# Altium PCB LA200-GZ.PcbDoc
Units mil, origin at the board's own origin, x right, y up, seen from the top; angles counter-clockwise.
Board outline 3789.56 x 3553.34 mil, 4 copper layers (Top Layer, GND, VCC, Bottom Layer), stack 30.634 mil thick; 139 components, 86 nets, 416 pads, 289 vias.
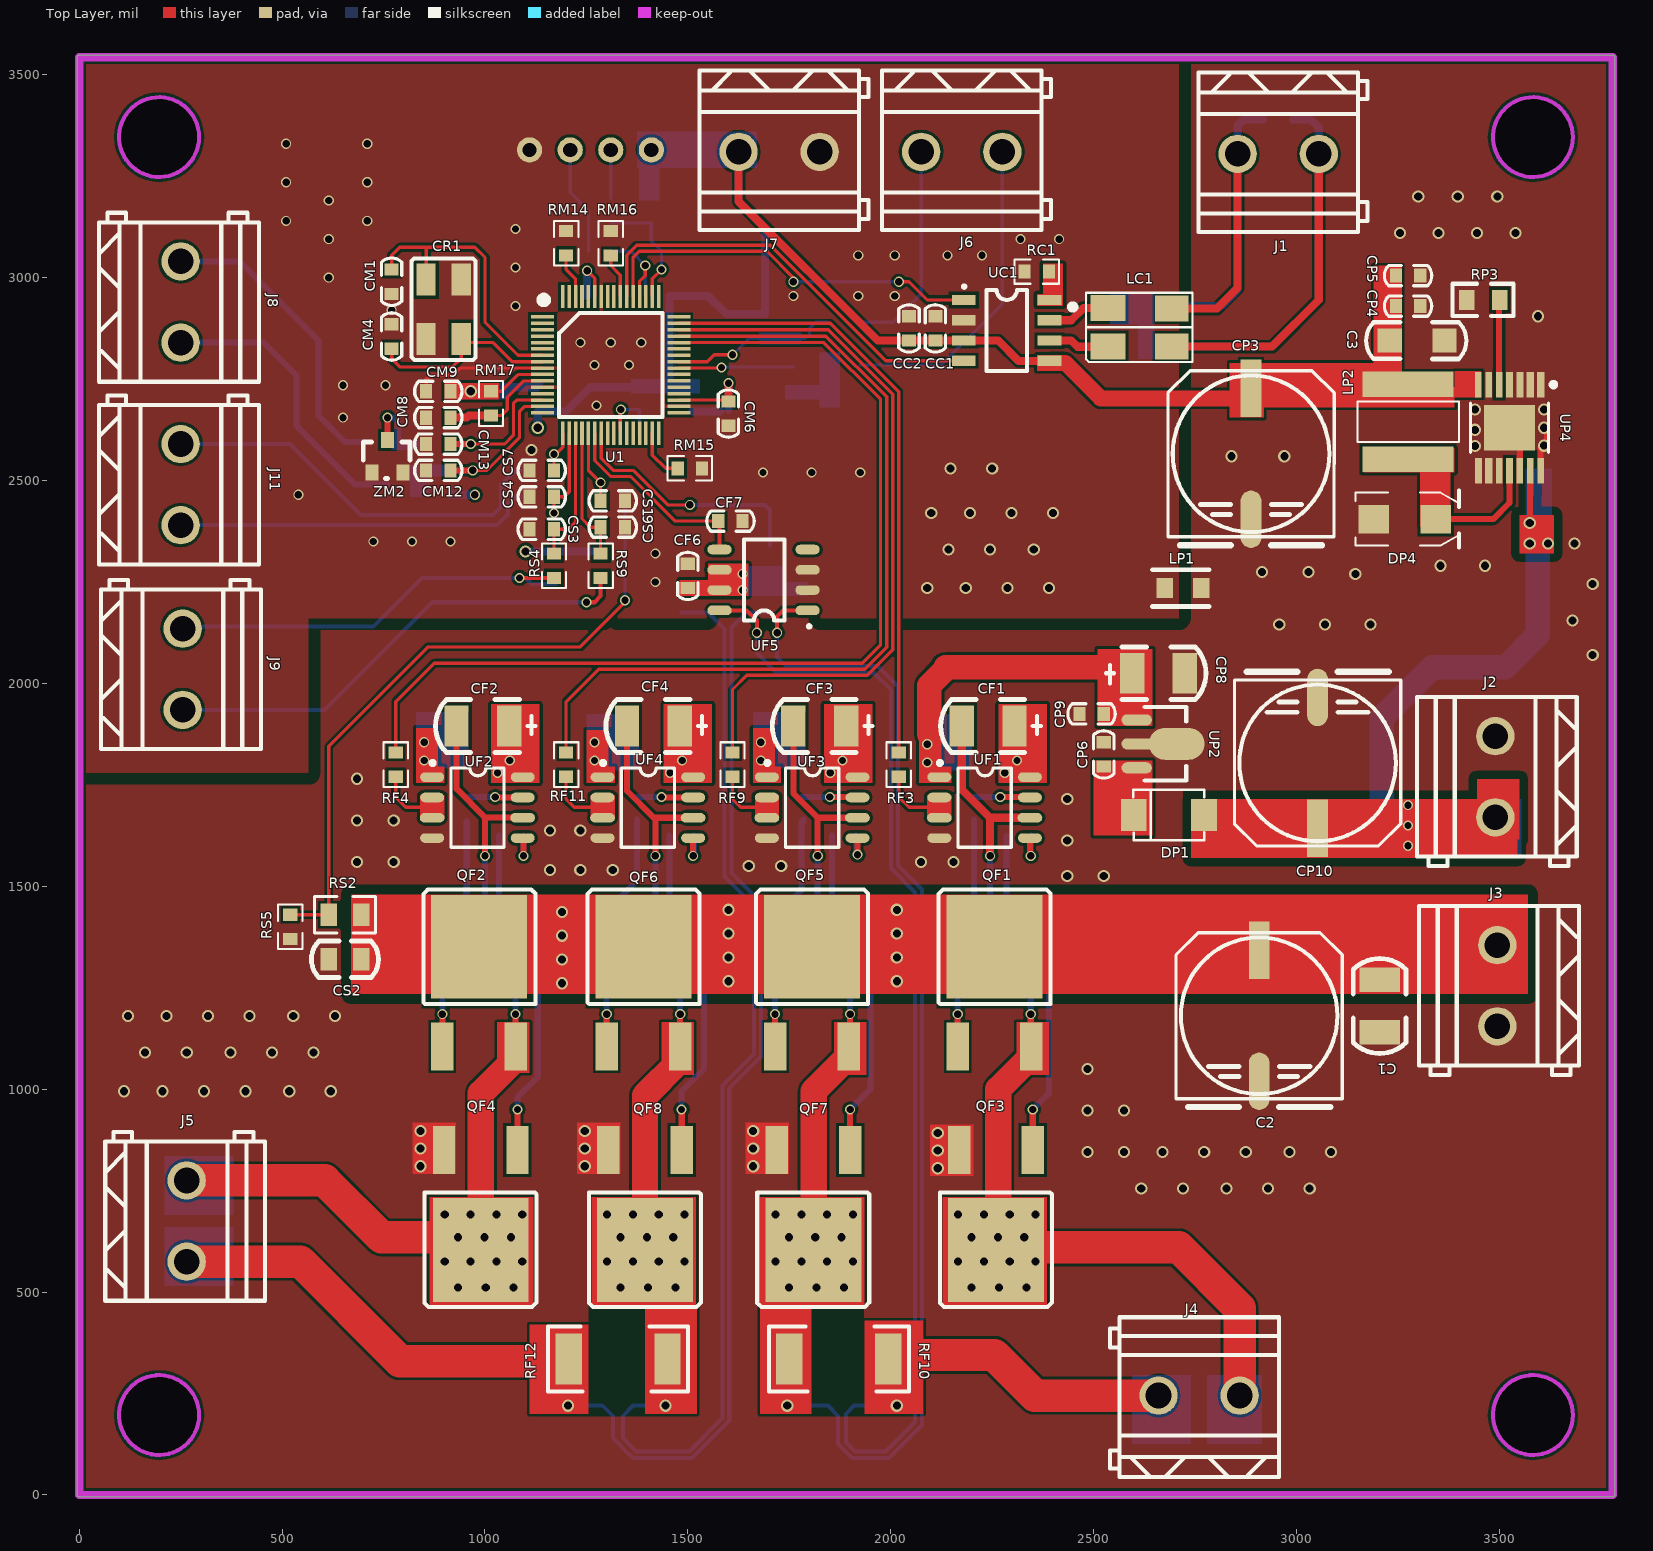
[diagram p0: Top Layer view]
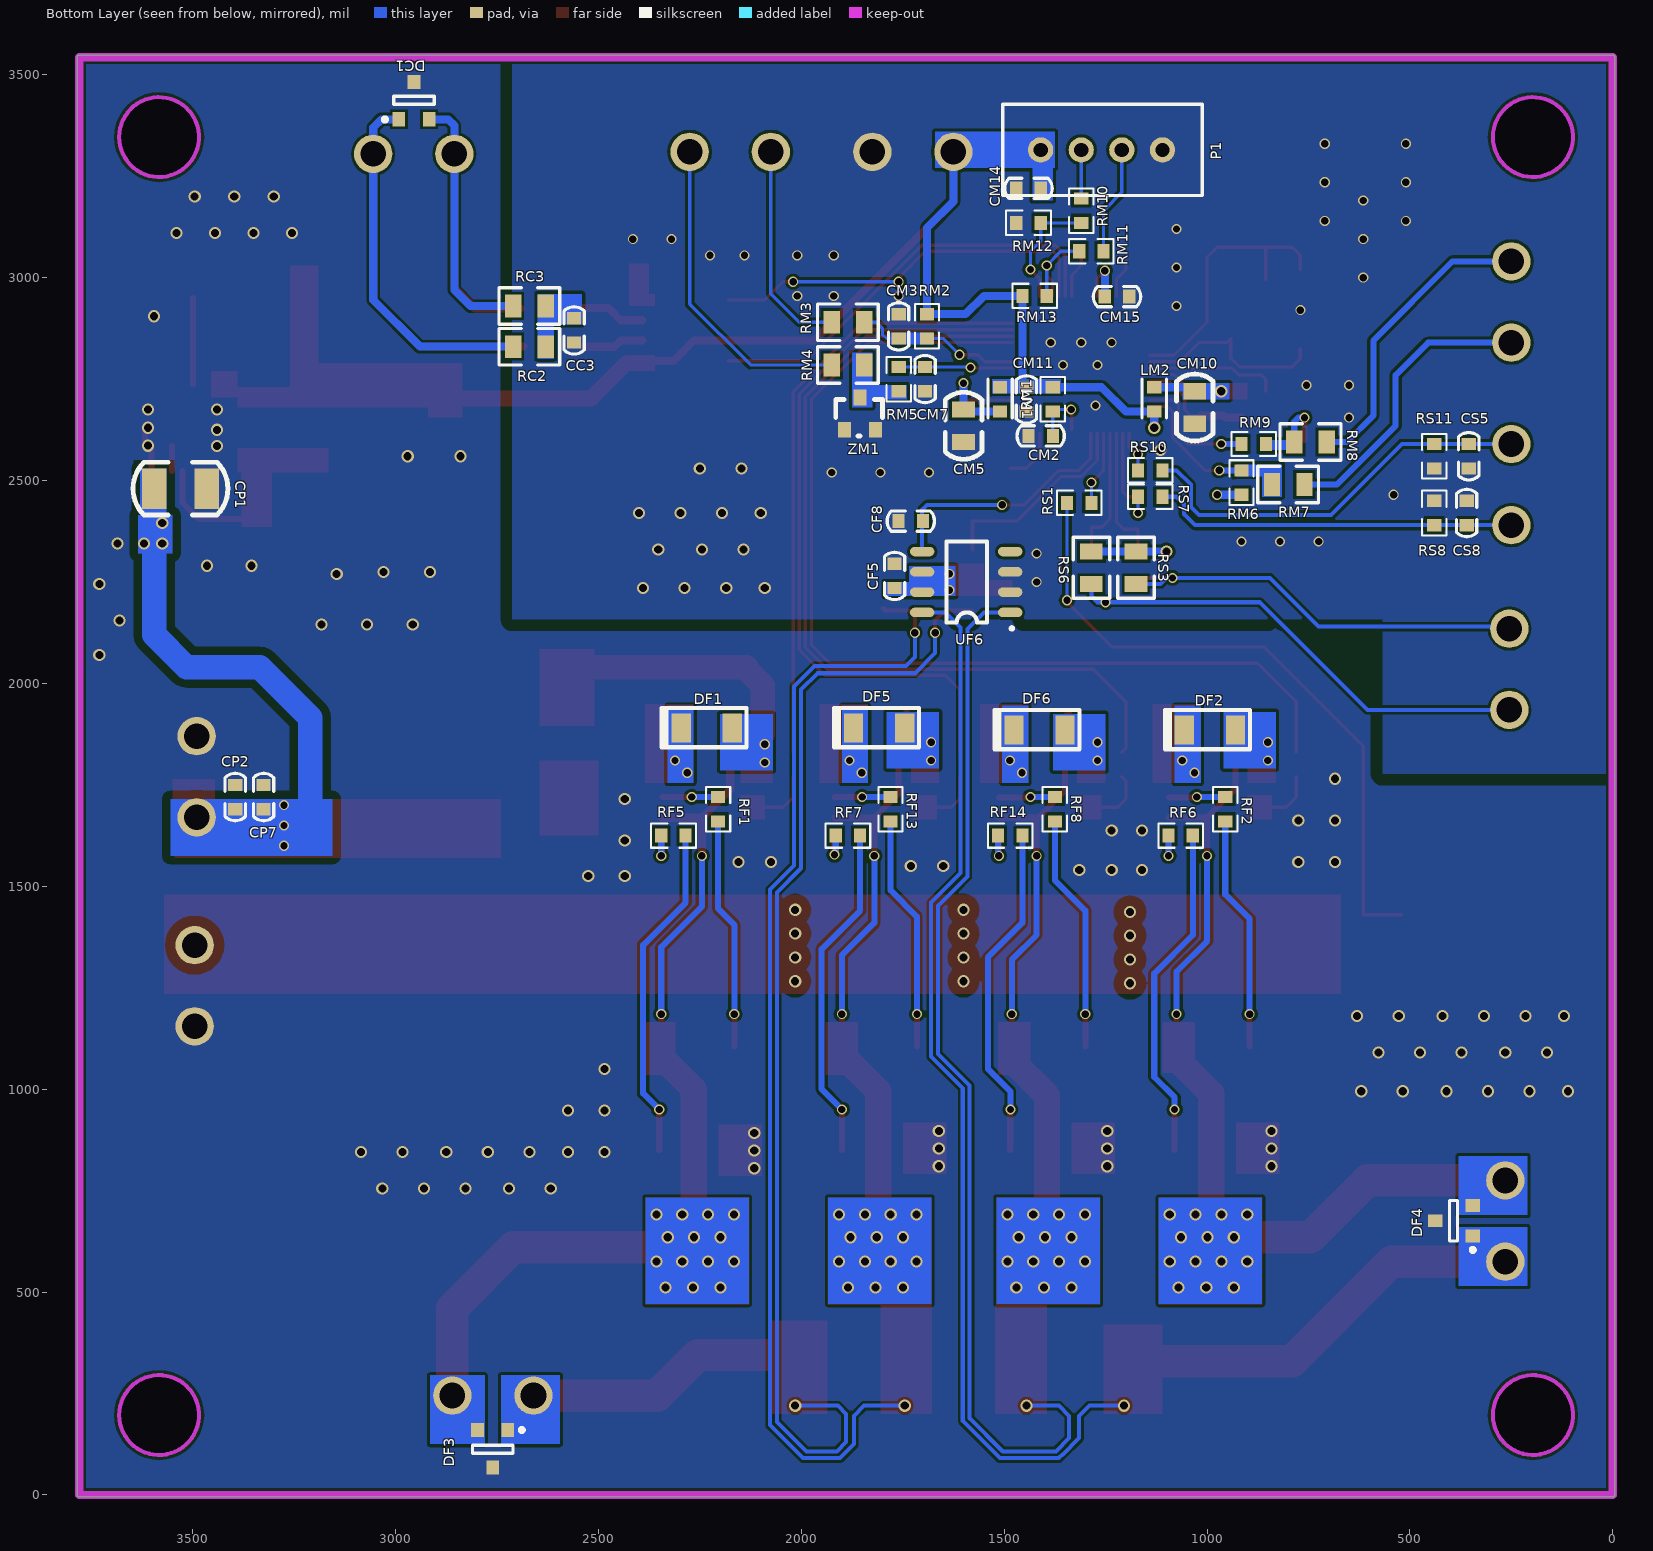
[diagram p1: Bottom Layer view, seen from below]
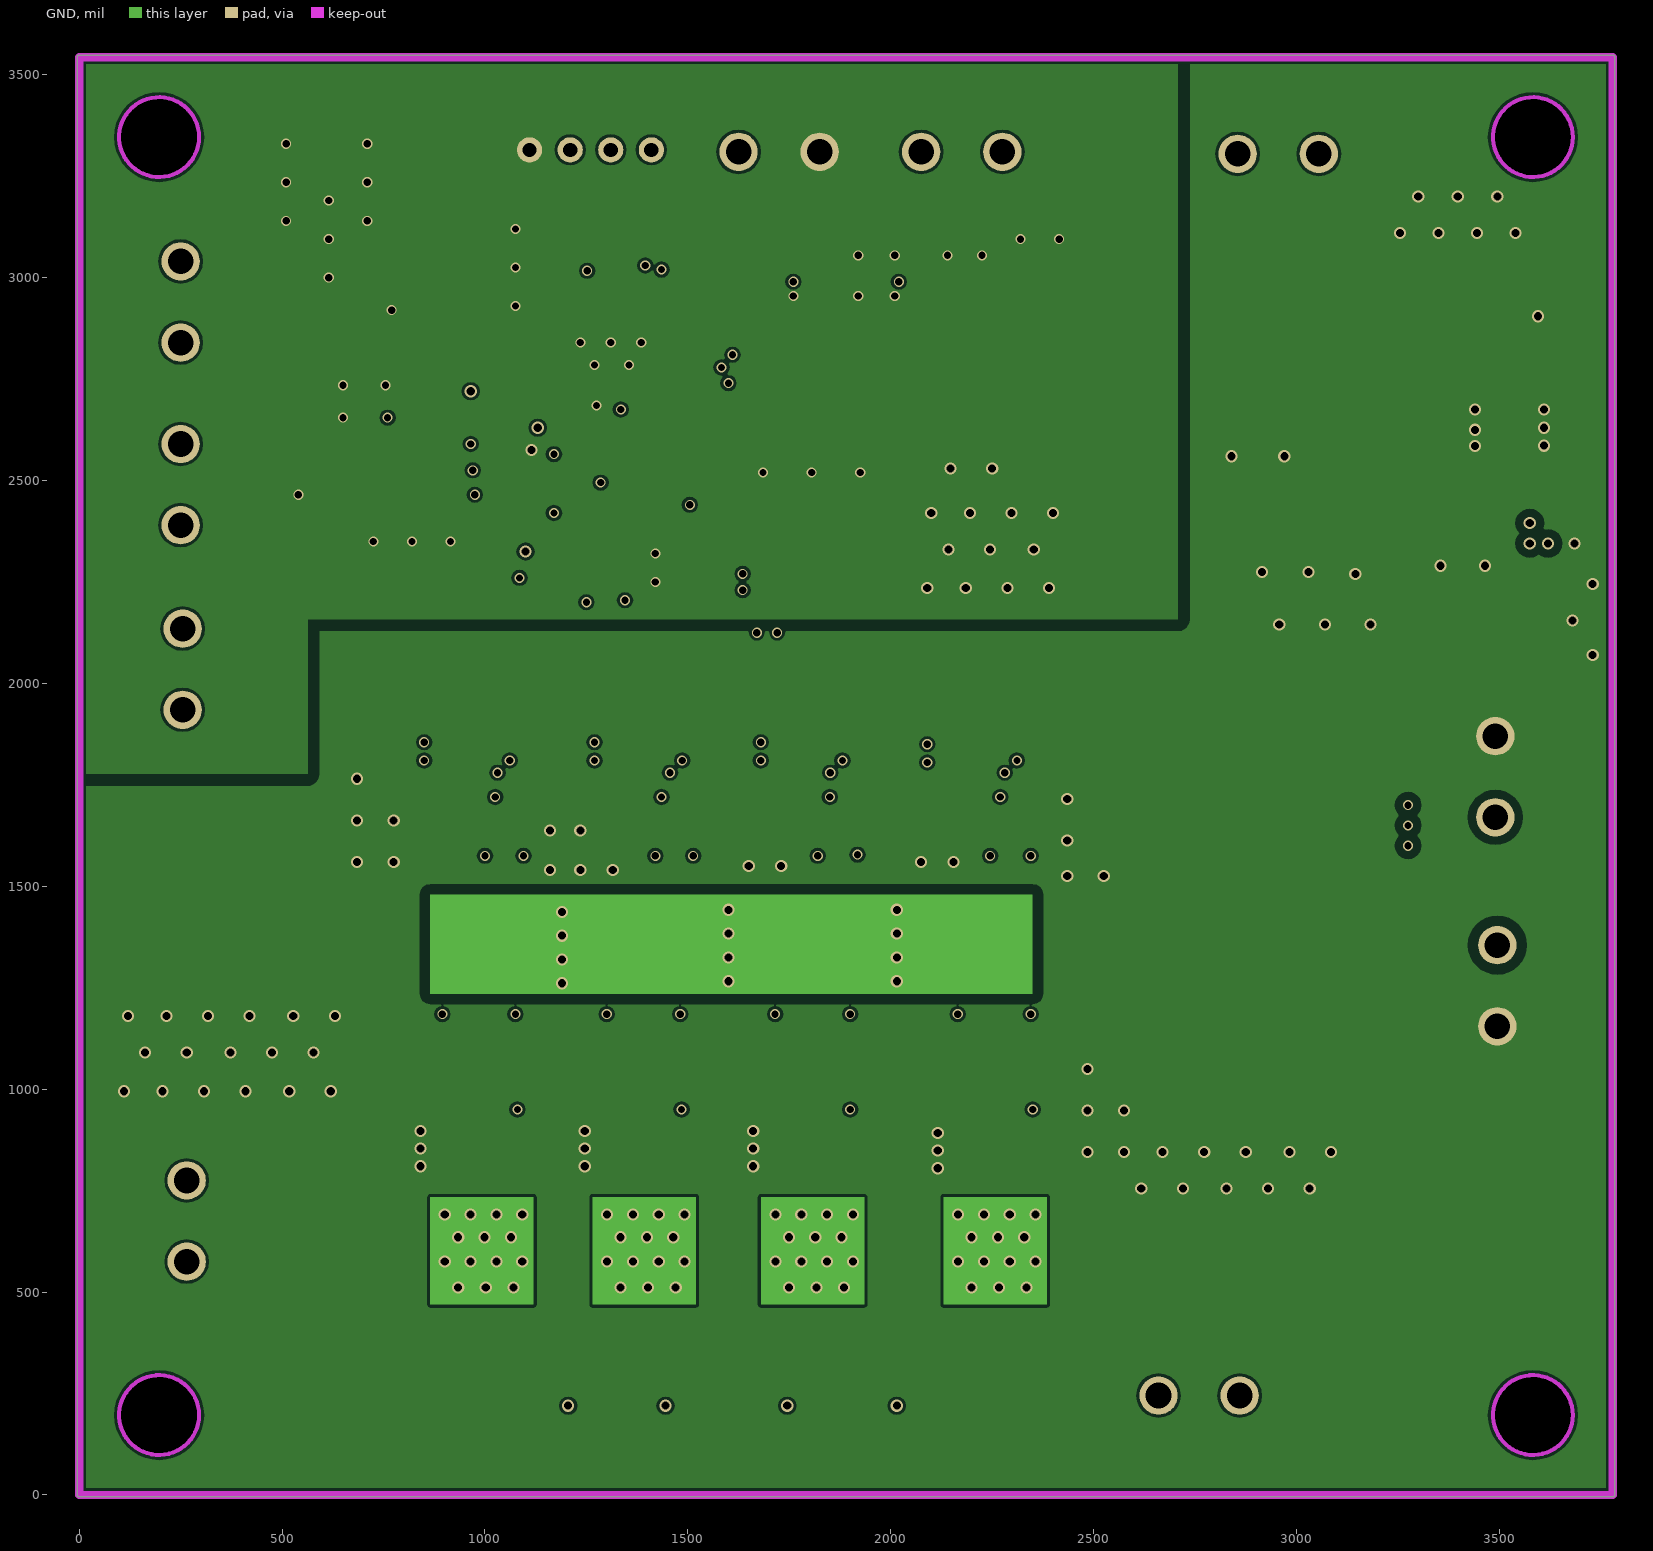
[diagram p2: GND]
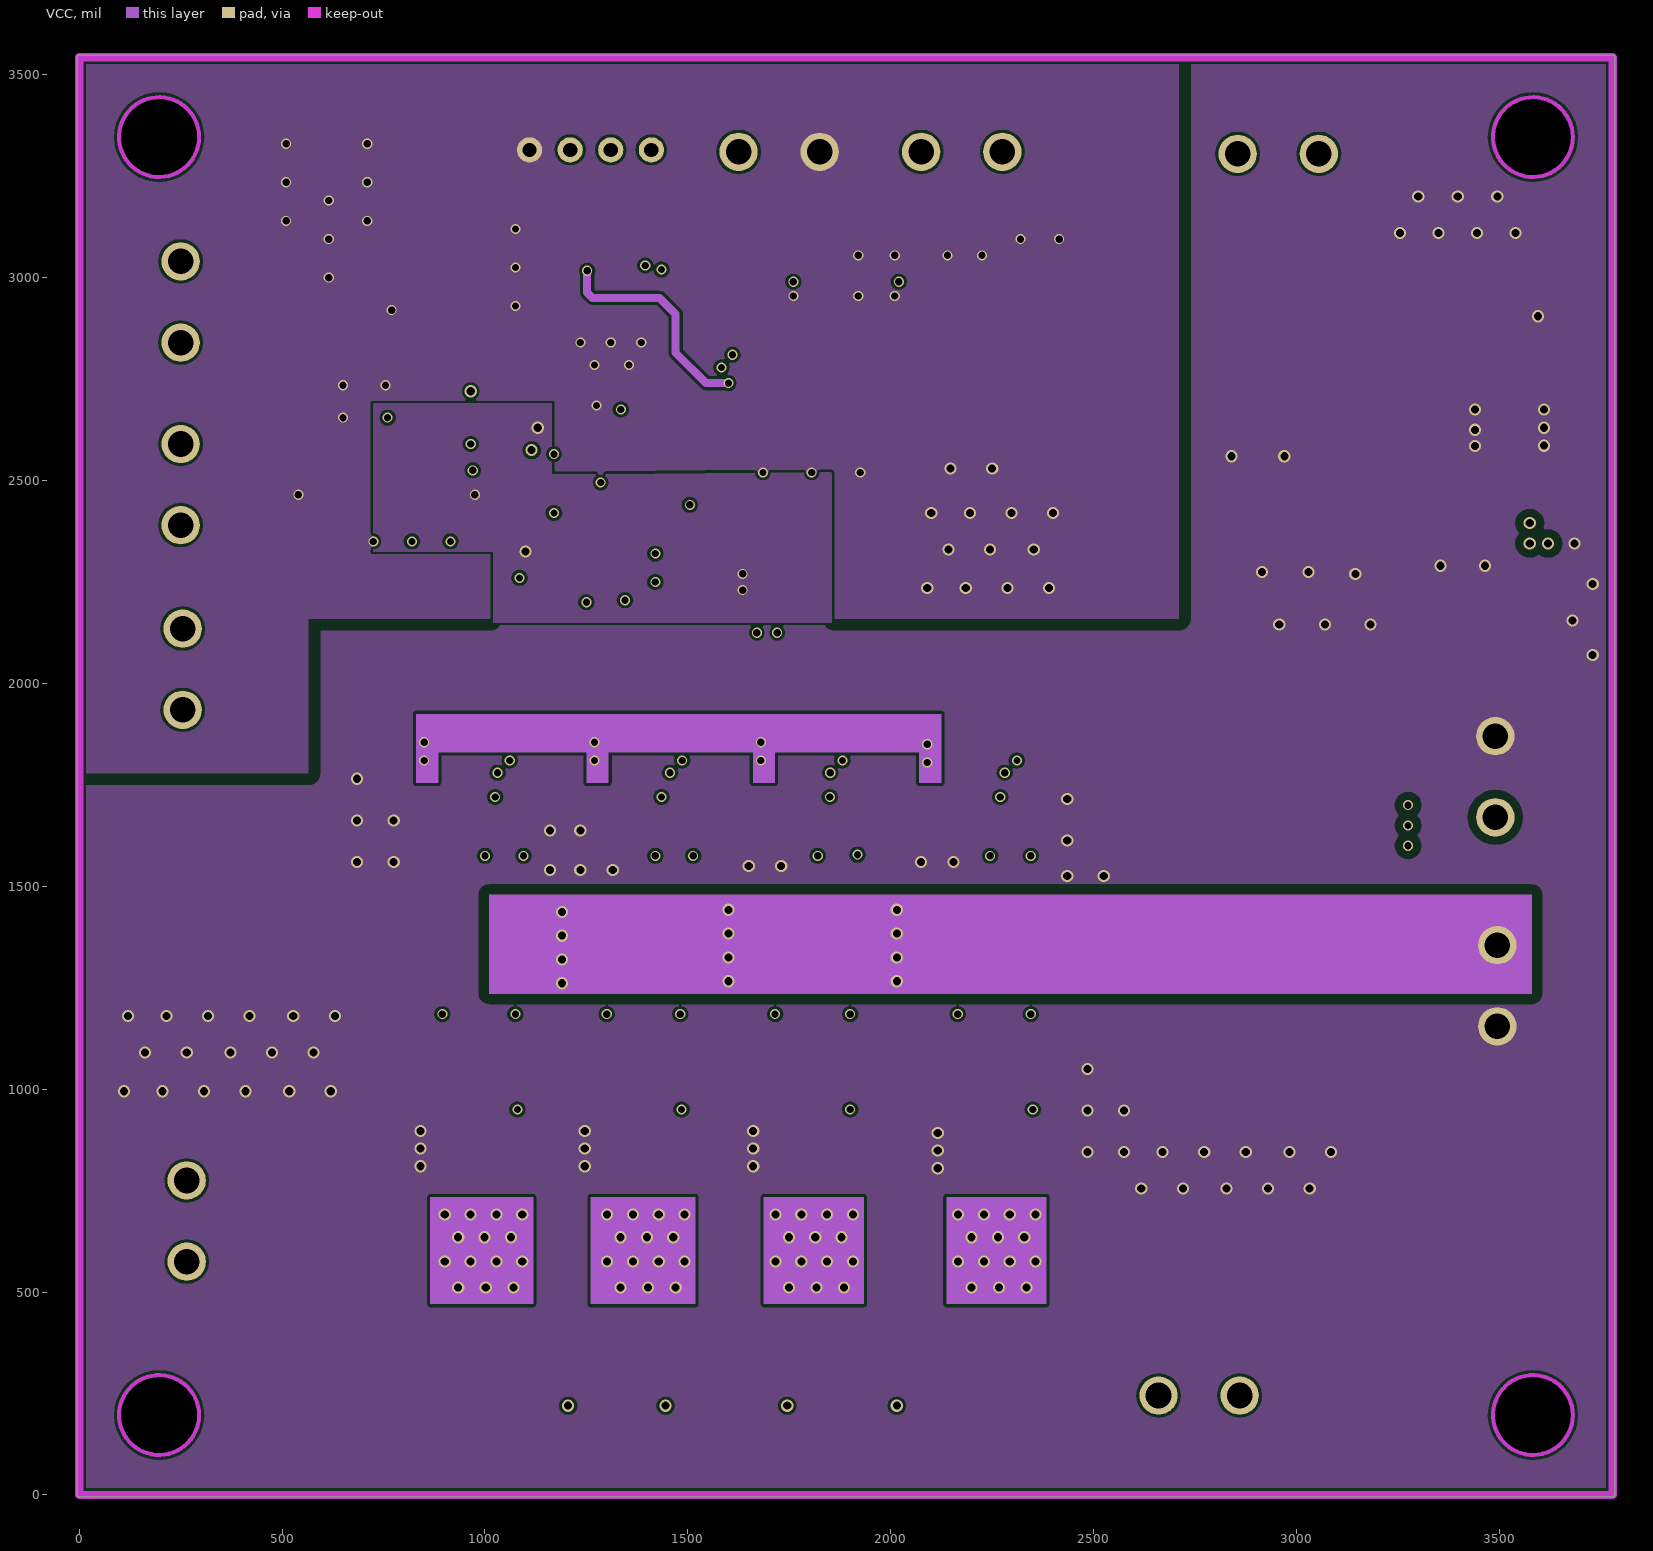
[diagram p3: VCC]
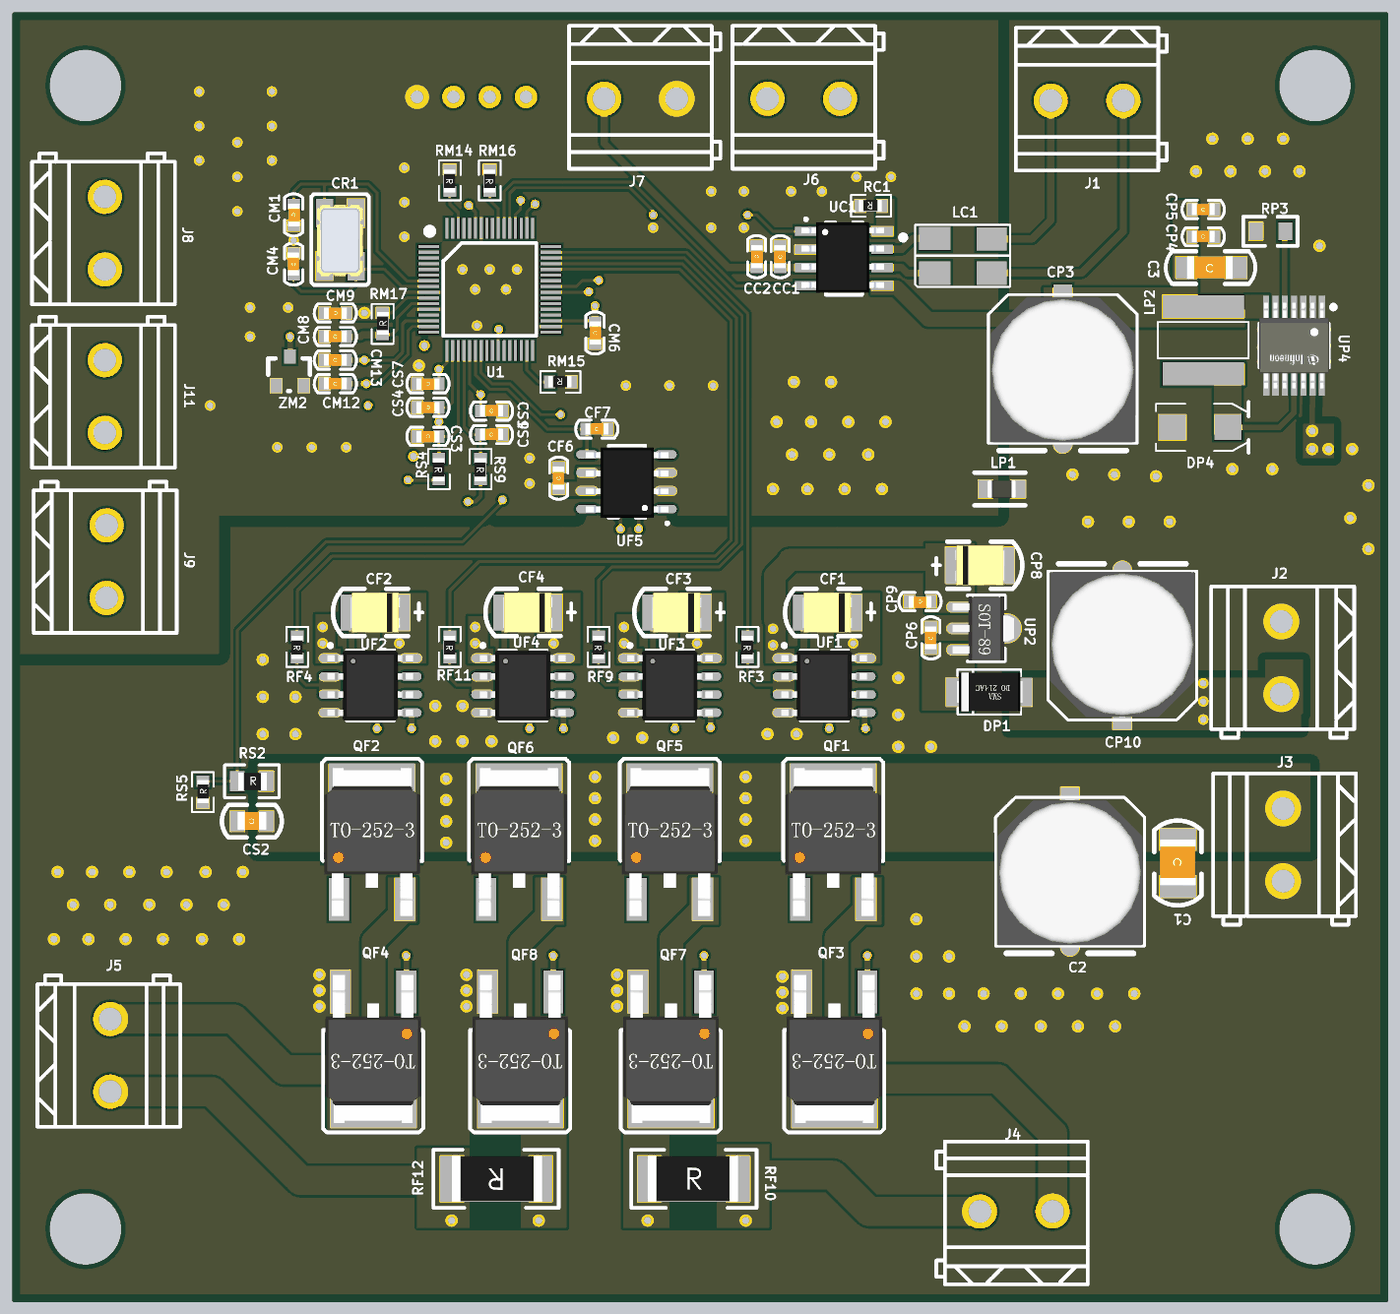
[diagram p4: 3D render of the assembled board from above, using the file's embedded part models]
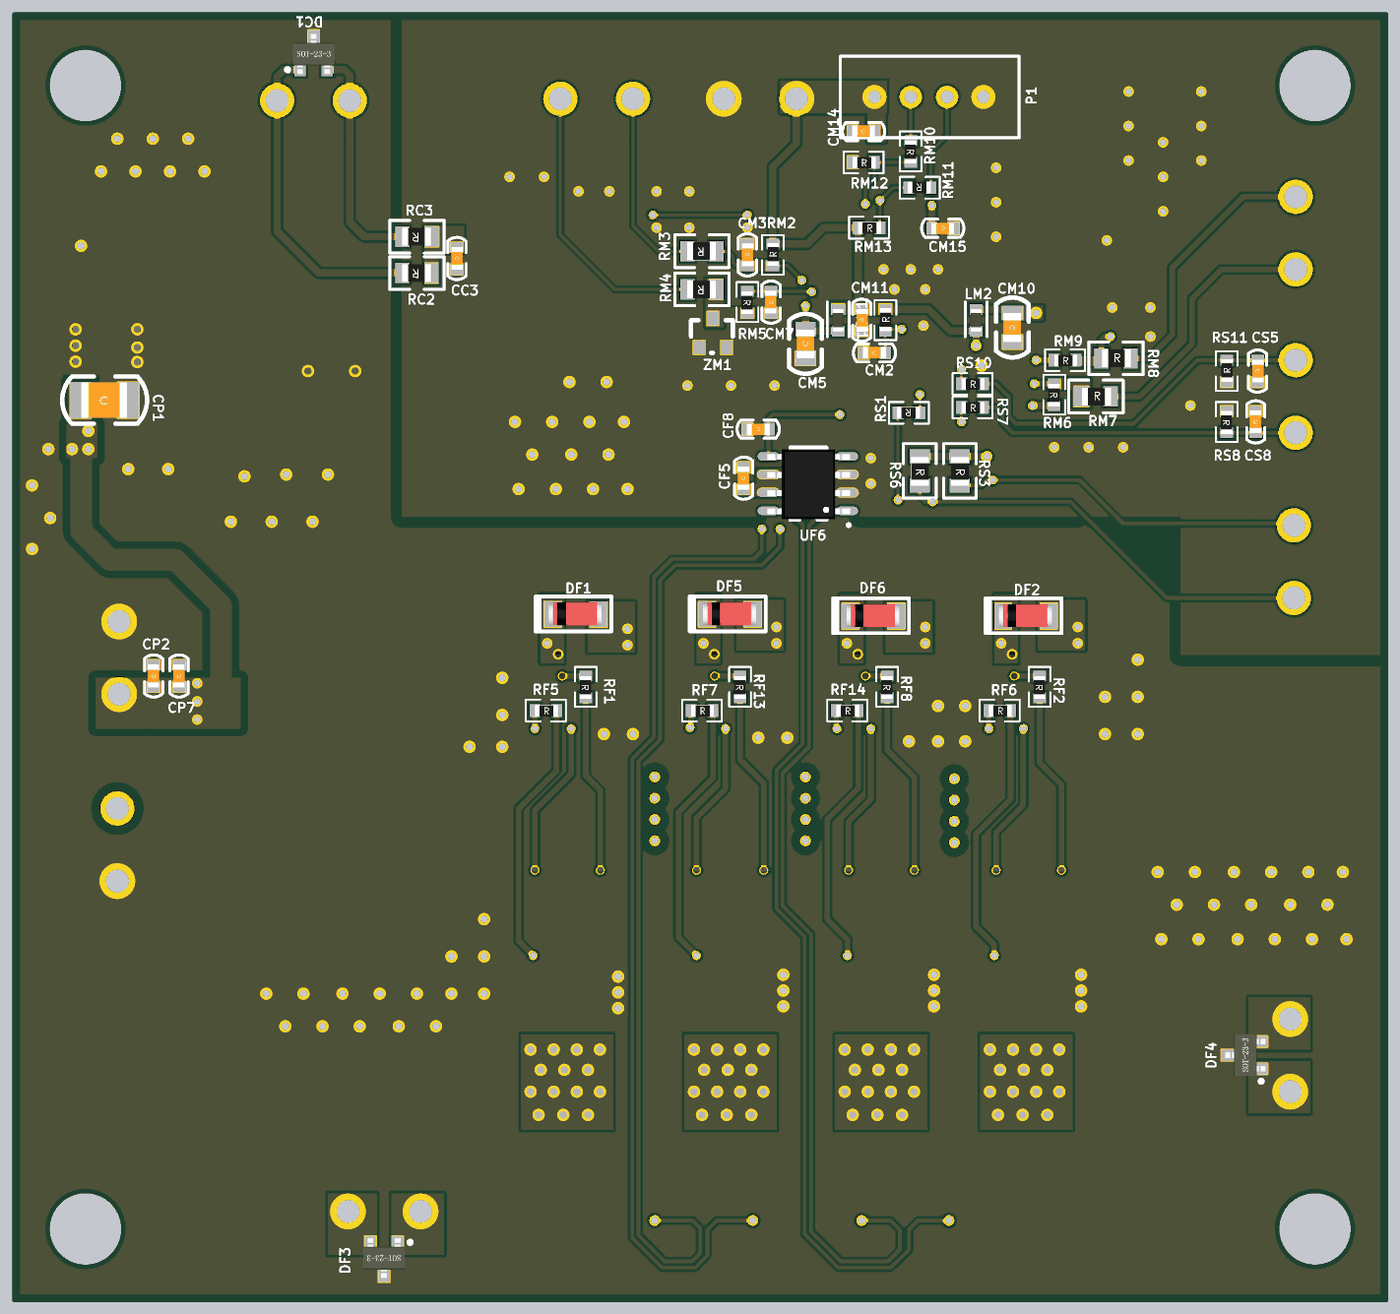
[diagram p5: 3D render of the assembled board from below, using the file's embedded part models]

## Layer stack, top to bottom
Top Solder: solder mask 0.4, Solder Resist, Dk 3.5
Top Layer: signal copper 1.4
Dielectric 1: core 10, FR-4, Dk 4.2
GND: signal copper 1.417
Dielectric 3: core 10, Dk 4.2
VCC: signal copper 1.417
Dielectric 2: prepreg 5, Dk 4.2
Bottom Layer: signal copper 1.4
Bottom Solder: solder mask 0.4, Solder Resist, Dk 3.5

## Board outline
-5.01,0 ccw(c0,0) 0,-5.01 3779.53,-5.01 ccw(c3779.53,0) 3784.54,0 3784.54,3543.31 ccw(c3779.53,3543.31) 3779.53,3548.32 0,3548.32 ccw(c0,3543.31) -5.01,3543.31
cut-out: 98.43,3346.46 ccw(c196.85,3346.46) 196.85,3248.03 ccw(c196.85,3346.46) 295.28,3346.46 ccw(c196.85,3346.46) 196.85,3444.88 ccw(c196.85,3346.46)
cut-out: 3484.25,3346.46 ccw(c3582.68,3346.46) 3582.68,3248.03 ccw(c3582.68,3346.46) 3681.1,3346.46 ccw(c3582.68,3346.46) 3582.68,3444.88 ccw(c3582.68,3346.46)
cut-out: 3484.25,196.85 ccw(c3582.68,196.85) 3582.68,98.43 ccw(c3582.68,196.85) 3681.1,196.85 ccw(c3582.68,196.85) 3582.68,295.28 ccw(c3582.68,196.85)
cut-out: 98.43,196.85 ccw(c196.85,196.85) 196.85,98.43 ccw(c196.85,196.85) 295.28,196.85 ccw(c196.85,196.85) 196.85,295.28 ccw(c196.85,196.85)

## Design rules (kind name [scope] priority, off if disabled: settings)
Clearance IGN1 [InNet('PGND') vs InNet('GND')] p1: gap=30
Clearance Clearance_5 [InNet('VBAT')] p2: gap=25
Clearance Clearance_4 [InNet('MAIN_PWR')] p3 off: gap=20
Clearance MARK1 [InNet('MARK1')] p4: gap=22
Clearance MARK2 [InNet('MARK2')] p5: gap=22
Clearance LOW2_OUT [InNet('LOW2_OUT')] p6 off: gap=10
Clearance Clearance_2 [InPolygon vs OnLayer('Keep-Out Layer')] p7 off: gap=15
Clearance VBAT [InNet('VBAT')] p8: gap=30
Clearance "POWER 28v" [InNet('28V')] p9: gap=20
Clearance VCC_5V [InNet('VCC_5V')] p10 off: gap=10
Clearance VPROT_5V [InNet('VPROT_5V')] p11 off: gap=10
Clearance [All] p12 off: gap=20
Clearance Clearance_1 [All] p13 off: gap=10
Clearance Clearance_3 [All] p14: gap=7
ComponentClearance [All] p1: gap=0 collisioncheckmode=3 verticalgap=0 showdistances=TRUE
Height [All] p1 off: minheight=0 maxheight=10000 prefheight=500
HoleSize [All] p1: absolutevalues=TRUE maxlimit=2000 minlimit=0 maxpercent=80.000 minpercent=20.000
HoleToHoleClearance [All] p1: gap=5 allowstackedmicrovias=TRUE
MinimumSolderMaskSliver [All] p1: minsoldermaskwidth=0
MinimumSolderMaskSliver SilkscreenOverComponentPads [All] p2: minsoldermaskwidth=10
NetAntennae [All] p1: netantennaetolerance=5
PlaneClearance PlaneClearance_4 [InNet('KEY')] p1: clearance=30
PlaneClearance PlaneClearance_3 [InNet('VBAT')] p2: clearance=30
PlaneClearance PlaneClearance_2 [InNet('INJOUT1')] p3: clearance=25
PlaneClearance PlaneClearance_1 [InNet('IGN1')] p4: clearance=40
PlaneClearance [All] p5: clearance=20
PlaneConnect [All] p1: planeconnectstyle=Direct reliefexpansion=20 reliefentries=4 reliefconductorwidth=10 reliefairgap=10
PolygonConnect [IsPoly vs IsVia] p1: connectstyle=Direct reliefconductorwidth=10 reliefentries=4 polygonreliefangle="90 Angle" airgapwidth=10
PolygonConnect PolygonConnect_1 [All] p2: connectstyle=Direct reliefconductorwidth=15 reliefentries=4 polygonreliefangle="90 Angle" airgapwidth=20
RoutingLayers [All] p1: top layer_v5=TRUE mid layer 1_v5=FALSE mid layer 2_v5=TRUE bottom layer_v5=TRUE
RoutingVias [All] p1: holewidth=60 width=100 viastyle="Through Hole" minholewidth=16 minwidth=24 maxholewidth=20 maxwidth=35
SilkToSilkClearance [All] p1 off: silktosilkclearance=0
SilkToSolderMaskClearance [IsPad] p1: minsilkscreentomaskgap=0 clearancetoexposedcopper=TRUE
SolderMaskExpansion [All] p1: expansion=2
Width [All] p1: maxlimit=200 minlimit=6 preferedwidth=10 minimp=50.000000 maximp=50.000000 favimp=50.000000
19 further rules are at their usual default settings.

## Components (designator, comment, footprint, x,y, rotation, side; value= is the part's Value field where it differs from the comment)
C1 "C1210 0.1uF/100V" C1210 3205,1270 r270 top
C2 "E10T10_220uF/50V" E10T10 2905,1020 r90 top
C3 "C1206 10uF/50V" C1206 3230,2845 r0 top
CC1 "C0603_0.1uF" C0603 2110,2845 r90 top
CC2 "C0603_1uF/10V" C0603 2045,2905 r270 top
CC3 "C0603_4.7nF" C0603 2560,2900 r270 bottom
CF1 "CtanB_10uF" CTANB 2305,1895 r180 top
CF2 "CtanB_10uF" CTANB 1060,1895 r180 top
CF3 "CtanB_10uF" CTANB 1890,1895 r180 top
CF4 "CtanB_10uF" CTANB 1480,1895 r180 top
CF5 "C0603_0.1uF/50V" C0603 1770,2235 r90 bottom
CF6 "C0603_0.1uF/50V" C0603 1500,2235 r90 top
CF7 "C0603_100pF/50V" C0603 1575,2400 r0 top
CF8 "C0603_100pF/50V" C0603 1700,2400 r0 bottom
CM1 "C0603_15pF/50V" C0603 770,3020 r270 top
CM2 "C0603 0.1uF/50V" C0603 1440,2610 r180 bottom
CM3 "C0603_100pF/50V" C0603 1760,2910 r270 bottom
CM4 "C0603_15pF/50V" C0603 770,2825 r90 top
CM5 "C0805_10uF/16V" C0805 1600,2595 r90 bottom
CM6 "C0603 0.1uF/50V" C0603 1600,2695 r270 top
CM7 "C0603_100pF/50V" C0603 1695,2720 r90 bottom
CM8 "C0603 0.1uF/50V" C0603 855,2655 r0 top
CM9 "C0603 0.1uF/50V" C0603 915,2720 r180 top
CM10 "C0805_10uF/16V" C0805 1030,2720 r270 bottom
CM11 "C0603 0.1uF/50V" C0603 1445,2730 r270 bottom
CM12 "C0603_100pF/50V" C0603 855,2525 r0 top
CM13 "C0603_100pF/50V" C0603 855,2590 r0 top
CM14 "C0603 0.1uF/50V" C0603 1470,3220 r180 bottom
CM15 "C0603 0.1uF/50V" C0603 1191.89,2953.31 r0 bottom
CP1 "C1210_10uF/50V" C1210 3595,2480 r180 bottom
CP2 "C0603_0.1uF/50V" C0603 3395,1690 r90 bottom
CP3 "CE101010M-470uF/25V" E10T10 2885,2405 r90 top
CP4 "C0603_0.1uF/50V" C0603 3245,2930 r0 top
CP5 "C0603 10nF/50V" C0603 3245,3005 r0 top
CP6 "C0603_0.22uF/50V" C0603 2525,1795 r90 top
CP7 "C0603_0.1uF/50V" C0603 3325,1690 r90 bottom
CP8 "CtanB_10uF/25V" CTANB 2595,2025 r0 top
CP9 "C0603_0.1uF/50V" C0603 2525,1925 r180 top
CP10 "E10T10_220uF/50V" E10T10 3055,1965 r270 top
CR1 "8MHz" "5.0*3.2*0.9mm AB" 855,2995 r270 top
CS1 "C0603 1uF/50V" C0603 1285,2450 r0 top
CS2 "C0805_1nF/100V" C0805 695,1320 r180 top
CS3 "C0603 0.1uF/50V" C0603 1170,2380 r180 top
CS4 "C0603_0.1uF/50V" C0603 1170,2460 r180 top
CS5 "C0603_10nF/50V" C0603 360,2390 r90 bottom
CS6 "C0603 0.1uF/50V" C0603 1285,2385 r0 top
CS7 "C0603_0.1uF/50V" C0603 1170,2525 r180 top
CS8 "C0603_10nF/50V" C0603 355,2590 r270 bottom
DC1 "SZNUP2105LT1G" SOT-23 2990,3390 r180 bottom
DF1 "LL4148" SOD-80 2170,1890 r0 bottom
DF2 "LL4148" SOD-80 930,1885 r0 bottom
DF3 "SM36T1G" SOT-23 2725,160 r0 bottom
DF4 "SM36T1G" SOT-23 345,640 r90 bottom
DF5 "LL4148" SOD-80 1745,1890 r0 bottom
DF6 "LL4148" SOD-80 1350,1885 r0 bottom
DP1 "FM404" D0-214AC 2680,1675 r180 top
DP4 "B360A" SMA-DIODE 3185,2405 r0 top
J1 "2Pin 5.08mm" CONN-TH_2P-P5.08_DB128L-5.08-2P 2955,3305 r180 top
J2 "2Pin 5.08mm" CONN-TH_2P-P5.08_DB128L-5.08-2P 3490,1770 r90 top
J3 "2Pin 5.08mm" CONN-TH_2P-P5.08_DB128L-5.08-2P 3495,1255 r90 top
J4 "2Pin 5.08mm" CONN-TH_2P-P5.08_DB128L-5.08-2P 2760,245 r0 top
J5 "2Pin 5.08mm" CONN-TH_2P-P5.08_DB128L-5.08-2P 265,675 r270 top
J6 "2Pin 5.08mm" CONN-TH_2P-P5.08_DB128L-5.08-2P 2175,3310 r180 top
J7 "2Pin 5.08mm" CONN-TH_2P-P5.08_DB128L-5.08-2P 1725,3310 r180 top
J8 "2Pin 5.08mm" CONN-TH_2P-P5.08_DB128L-5.08-2P 250,2940 r270 top
J9 "2Pin 5.08mm" CONN-TH_2P-P5.08_DB128L-5.08-2P 255,2035 r270 top
J11 "2Pin 5.08mm" CONN-TH_2P-P5.08_DB128L-5.08-2P 250,2490 r270 top
LC1 "10M/1K" ACT45B 2480,2790 r0 top
LM1 "ILBB0603ER102V" L0603 1510,2730 r270 bottom
LM2 "ILBB0603ER102V" L0603 1130,2730 r270 bottom
LP1 "MPZ2012S221ATD25" "L 0805" 2765,2235 r180 top
LP2 "NR6045T220M" L_6045 3275,2645 r90 top
P1 "4PIN/2.54mm/1A/250V" IDC-SIP-4P-2.54 1110,3315 r0 bottom
QF1 "FDD86567-F085" TO-252-3 2165,1105 r0 top
QF2 "FDD86567-F085" TO-252-3 895,1105 r0 top
QF3 "FDD86567-F085" TO-252-3 2350,850 r180 top
QF4 "FDD86567-F085" TO-252-3 1080,850 r180 top
QF5 "FDD86567-F085" TO-252-3 1715,1105 r0 top
QF6 "FDD86567-F085" TO-252-3 1300,1105 r0 top
QF7 "FDD86567-F085" TO-252-3 1900,850 r180 top
QF8 "FDD86567-F085" TO-252-3 1485,850 r180 top
RC1 "R0603_10K" R0603 2390,3015 r180 top
RC2 "R0805_62R" R0805 2630,2830 r0 bottom
RC3 "R0805_62R" R0805 2630,2930 r0 bottom
RF1 "R0603_10R" R0603 2205,1720 r270 bottom
RF2 "R0603_10R" R0603 955,1720 r270 bottom
RF3 "R0603_510R" R0603 2020,1830 r270 top
RF4 "R0603_510R" R0603 780,1830 r270 top
RF5 "R0603_10R" R0603 2345,1625 r180 bottom
RF6 "R0603_10R" R0603 1095,1625 r180 bottom
RF7 "R0603_10R" R0603 1780,1720 r270 bottom
RF8 "R0603_10R" R0603 1375,1720 r270 bottom
RF9 "R0603_510R" R0603 1610,1830 r270 top
RF10 "R2512_0.01R" R2512 1750,335 r0 top
RF11 "R0603_510R" R0603 1200,1830 r270 top
RF12 "R2512_0.01R" R2512 1450,335 r180 top
RF13 "R0603_10R" R0603 1915,1625 r180 bottom
RF14 "R0603_10R" R0603 1515,1625 r180 bottom
RM1 "R0603_10K" R0603 1380,2670 r90 bottom
RM2 "R0603_36K" R0603 1690,2850 r90 bottom
RM3 "R0805_1.5K" R0805 1845,2890 r0 bottom
RM4 "R0805_0.62K" R0805 1845,2785 r0 bottom
RM5 "R0603_51R" R0603 1760,2780 r270 bottom
RM6 "R0603_36K" R0603 915,2525 r270 bottom
RM7 "R0805_1.5K" R0805 840,2490 r180 bottom
RM8 "R0805_0.62K" R0805 785,2595 r180 bottom
RM9 "R0603_51R" R0603 915,2590 r180 bottom
RM10 "R0603_510R" R0603 1310,3195 r270 bottom
RM11 "R0603_510R" R0603 1255,3065 r0 bottom
RM12 "R0603_10K" R0603 1470,3135 r180 bottom
RM13 "R0603_10K" R0603 1455,2955 r180 bottom
RM14 "R0603_10K" R0603 1200,3115 r270 top
RM15 "R0603_10K" R0603 1535,2530 r180 top
RM16 "R0603_10K" R0603 1310,3115 r270 top
RM17 "R0603_0R" R0603 1015,2660 r90 top
RP3 "RP0805J-47K-1/4W" 0805_R 3420,2945 r0 top
RS1 "R0603_4.7K" R0603 1285,2445 r0 bottom
RS2 "R0805_100K" R0805 615,1430 r0 top
RS3 "R0805_4.02K" R0805 1175,2325 r270 bottom
RS4 "R0603_10K" R0603 1170,2320 r270 top
RS5 "R0603_15K" R0603 520,1370 r90 top
RS6 "R0805_4.02K" R0805 1285,2325 r270 bottom
RS7 "R0603_4.7K" R0603 1170,2460 r180 bottom
RS8 "R0603_240K" R0603 440,2450 r270 bottom
RS9 "R0603_10K" R0603 1285,2320 r270 top
RS10 "R0603_4.7K" R0603 1170,2525 r180 bottom
RS11 "R0603_240K" R0603 440,2530 r90 bottom
U1 "AC7815-LQFP64" LQFP-64_L10.0-W10.0-P0.50-LS12.0-BL-EP5.3 1275,2805 r0 top
UC1 "TLE6250G" PG-DSO-8 2180,2945 r0 top
UF1 "IRS2007STRPBF" SOIC-8L 2120,1770.91 r0 top
UF2 "IRS2007STRPBF" SOIC-8L 870,1770.91 r0 top
UF3 "IRS2007STRPBF" SOIC-8L 1695,1770.91 r0 top
UF4 "IRS2007STRPBF" SOIC-8L 1290,1770.91 r0 top
UF5 "AD8206YRZ" SO-8_NB 1795,2180 r180 top
UF6 "AD8206YRZ" SO-8_NB 1485,2175 r0 bottom
UP2 "L78L12ABUTR" SOT-89 2705,1850 r180 top
UP4 "TLF50201EL" SSOP14-EP2 3525,2630 r270 top
ZM1 "BZX84C5V1" SOT-23AK 1855,2705 r90 bottom
ZM2 "BZX84C5V1" SOT-23AK 760,2600 r90 top

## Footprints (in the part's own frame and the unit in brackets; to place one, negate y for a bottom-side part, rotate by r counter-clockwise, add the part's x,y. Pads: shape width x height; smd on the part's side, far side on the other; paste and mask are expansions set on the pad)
"5.0*3.2*0.9mm AB" [mm]
  rect 2x1.2 smd: 1(0,0) 2(3.7,0) 3(3.7,2.2) 4(0,2.2)
  silkscreen extent -1.32,-0.91 5.03,3.1, body extent -0.59,-0.51 4.41,2.69, height 1.15
0805_R [mil]
  rect 38x50 smd: 1(0,0) 2(81,0)
  silkscreen extent -35,-40 115,40
ACT45B [mm]
  rect 2.2x1.626 smd: 1(1.414,3.427) 2(1.412,1.012)
  rect 2.1x1.626 smd: 3(5.4,1.012) 4(5.4,3.4)
  silkscreen extent -0.9,0.05 6.7,4.39
C0603 [mil]
  rect 30x35 smd: 1(0,0) 2(60,0)
  silkscreen extent -28,-25 88,25, body extent -1,-15 61,17, height 35
C0805 [mil]
  rect 40x56 smd: 1(0,0) 2(80,0)
  silkscreen extent -43,-45 123,45, body extent 0,-25 80,24, height 36
C1206 [mil]
  rect 60x60 smd: 1(-0.25,0.08) 2(134.75,0.08)
  silkscreen extent -58,-45 189,45, body extent 0,-31 126,32, height 37
C1210 [mil]
  rect 60x100 smd: 1(0,0) 2(130,0)
  silkscreen extent -52,-65 182,65, body extent 0,-49 126,49, height 37
CONN-TH_2P-P5.08_DB128L-5.08-2P [mm]
  round 2.4 hole 1.6: 1(-2.54,0) 2(2.54,0)
  silkscreen extent -5.59,-5.1 4.99,4.9
CTANB [mil]
  rect 60x100 smd: 1(0,0) 2(130,0)
  silkscreen extent -65,-65 182,65, body extent -4,-55 134,55, height 75
D0-214AC [mm]
  rect 1.6x2 smd: 1(-2.337,-0.025) 2(2.063,-0.025)
  silkscreen extent -2.36,-1.6 2.08,1.55, body extent -2.48,-1.38 2.12,1.32, height 2.4
E10T10 [mm]
  rect 3.6x1.3 smd: 1(8.189,-0.076)
  oval 3.6x1.3 smd: 2(-0.011,-0.076)
  silkscreen extent -1.63,-5.28 9.29,5.13, body extent -1.07,-5.16 9.09,5, height 11.92
IDC-SIP-4P-2.54 [mil]
  round 62 hole 35: 1(0,0) 2(100,0) 3(200,0) 4(300,0)
  silkscreen extent -98,-112 394,112
L0603 [mil]
  rect 30x35 smd: 1(0,0) 2(60,0)
  silkscreen extent -20,-30 75,30, body extent -1,-16 62,16, height 35
"L 0805" [mil]
  rect 40.31x50 smd: 1(-0.25,-0.08) 2(89.75,-0.08)
  silkscreen extent -20,-45 120,45, body extent 6,-25 84,25, height 47
L_6045 [mm]
  rect 1.6x5.7 smd: 1(-2.35,0) 2(2.35,0)
  silkscreen extent -1.27,-3.17 1.27,3.17
LQFP-64_L10.0-W10.0-P0.50-LS12.0-BL-EP5.3 [mm]
  rect 1.45x0.22 smd: 1(-3.386,2.492) 2(-3.386,2.092) 3(-3.386,1.692) 4(-3.386,1.292) 5(-3.386,0.892) 6(-3.386,0.492) 7(-3.386,0.092) 8(-3.386,-0.308) 9(-3.386,-0.708) 10(-3.386,-1.108) 11(-3.386,-1.508) 12(-3.386,-1.908) 13(-3.386,-2.308) 14(-3.386,-2.708) 15(-3.386,-3.108) 16(-3.386,-3.508) 33(5.164,-3.508) 34(5.164,-3.108) 35(5.164,-2.708) 36(5.164,-2.308) 37(5.164,-1.908) 38(5.164,-1.508) 39(5.164,-1.108) 40(5.164,-0.708) 41(5.164,-0.308) 42(5.164,0.092) 43(5.164,0.492) 44(5.164,0.892) 45(5.164,1.292) 46(5.164,1.692) 47(5.164,2.092) 48(5.164,2.492)
  rect 0.22x1.45 smd: 17(-2.111,-4.783) 18(-1.711,-4.783) 19(-1.311,-4.783) 20(-0.911,-4.783) 21(-0.511,-4.783) 22(-0.111,-4.783) 23(0.289,-4.783) 24(0.689,-4.783) 25(1.089,-4.783) 26(1.489,-4.783) 27(1.889,-4.783) 28(2.289,-4.783) 29(2.689,-4.783) 30(3.089,-4.783) 31(3.489,-4.783) 32(3.889,-4.783) 49(3.889,3.767) 50(3.489,3.767) 51(3.089,3.767) 52(2.689,3.767) 53(2.289,3.767) 54(1.889,3.767) 55(1.489,3.767) 56(1.089,3.767) 57(0.689,3.767) 58(0.289,3.767) 59(-0.111,3.767) 60(-0.511,3.767) 61(-0.911,3.767) 62(-1.311,3.767) 63(-1.711,3.767) 64(-2.111,3.767)
  silkscreen extent -3.45,-3.76 4.14,3.69
PG-DSO-8 [mm]
  rect 1.5x0.65 smd: 1(0,0) 2(0,-1.27) 3(0,-2.54) 4(0,-3.81) 5(5.36,-3.81) 6(5.36,-2.54) 7(5.36,-1.27) 8(5.36,0)
  silkscreen extent -0.07,-4.44 3.96,0.94, body extent -0.3,-4.29 5.48,0.61, height 1.45
R0603 [mil]
  rect 30x35 smd: 1(0,0) 2(60,0)
  silkscreen extent -25,-30 85,30, body extent 0,-17 63,15, height 21
R0805 [mil]
  rect 40x56 smd: 1(0,0) 2(80,0)
  silkscreen extent -35,-45 115,45, body extent 2,-25 81,24, height 21
R2512 [mil] "Chip Capacitor, Body 2.54x1.27mm, IPC High Density"
  rect 65x126 smd: 1(0,0) 2(243.56,-0.15)
  silkscreen extent -50,-80 295,80, body extent -4,-63 244,63, height 25
SMA-DIODE [mil]
  rect 74.8x70 smd: A(5,0) K(158.54,0)
  silkscreen extent -40,-70 215,70
SO-8_NB [mm]
  oval 1.52x0.6 smd: 1(0,0) 2(0,-1.27) 3(0,-2.54) 4(0,-3.81) 5(5.512,-3.81) 6(5.512,-2.54) 7(5.512,-1.27) 8(5.512,0)
  silkscreen extent -0.2,-4.44 3.99,1.1, body extent -0.19,-4.31 5.59,0.6, height 1.45
SOD-80 [mm]
  rect 1.2x1.8 smd: 1(0,0) 2(3.2,0)
  silkscreen extent -0.9,-1.25 4.42,1.2, body extent -0.22,-0.83 3.48,0.77, height 1.61
SOIC-8L [mm] "SOIC, 8-Leads, Body 4.9x3.9mm, Pitch 1.27mm, IPC Medium Density"
  oval 1.5x0.6 smd: 1(-0.006,-0.051) 2(-0.006,-1.321) 4(-0.006,-3.861) 5(5.664,-3.861) 7(5.664,-1.321) 8(5.664,-0.051)
  oval 1.55x0.6 smd: 3(-0.006,-2.591) 6(5.664,-2.591)
  silkscreen extent -0.1,-4.44 4.5,0.96, body extent -0.18,-4.41 5.82,0.49, height 1.7
SOT-23 [mm]
  rect 0.8x0.9 smd: 1(-0.046,0) 2(1.854,0) 3(0.904,2.343)
  silkscreen extent -1.05,-0.12 2.17,1.45, body extent -0.55,-0.3 2.35,2.5, height 1.2
SOT-23AK [mil]
  rect 39x32 smd: A(-80,38) K(0,0) NC(-80,-38)
  silkscreen extent -95,-55 -5,60
SOT-89 [mm] "SOT23, 6-Leads, Body 2.9x1.6mm, Pitch 0.95mm, Lead Span 2.7mm, IPC Medium Density"
  oval 1.9x0.7 smd: 1(2.507,-1.527) 3(2.507,1.473)
  oval 3.5x2 smd: 2(0.007,-0.027)
  oval 2.1x0.7 smd: 2(2.407,-0.027)
  silkscreen extent -0.59,-2.33 2.01,2.27, body extent -1.24,-2.28 3.06,2.22, height 1.51
SSOP14-EP2 [mm]
  rect 2.85x3.2 smd paste-0.555 mask+0: 0(0,0)
  rect 1.6x0.45 smd paste+0 mask+0: 1(-2.7,1.95) 2(-2.7,1.3) 3(-2.7,0.65) 8(2.7,-1.95) 9(2.7,-1.3)
  rect 1.6x0.42 smd paste+0 mask+0: 4(-2.7,0) 5(-2.7,-0.65) 6(-2.7,-1.3)
  rect 1.6x0.419 smd paste+0 mask+0: 7(-2.7,-1.95) 10(2.7,-0.65) 11(2.7,0) 12(2.7,0.65) 13(2.7,1.3) 14(2.7,1.95)
  silkscreen extent -2.85,-2.45 1.55,2.9, body extent -3,-2.45 3,2.45, height 1.71
TO-252-3 [mm]
  rect 1.4x3 smd: 1(0,0) 3(4.6,0)
  rect 6x6.5 smd: 2(2.3,6.25)
  silkscreen extent -1.19,2.67 5.82,9.83, body extent -1.04,-1.18 5.66,9.18, height 2.41

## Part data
C1: library part 3170014005, "C1210 0.1uF/50V 10%"
C2 CP10: library part 3172690040, "E10T10 220uF/50V 20%"
C3: library part 3172530019, "C1206 10uF/50V  10%"
CC1 CC2 CF5 CF6 CM2 CM6 CM8 CM9 CM11 CM14 CM15 CP2 CP4 CP7 CP9 CS3 CS4 CS6 CS7: library part 3170011015, "C0603 0.1uF/50V 10%"
CC3: library part 3170011009, "C0603 4.7nF/50V 5% X7R"
CF1 CF2 CF3 CF4 CP8: library part 3172690034, "CtanB(1210) 10uF/25V 10%"
CF7 CF8 CM3 CM7 CM12 CM13: library part 3170011003, "C0603 100pF/50V 5%"
CM1 CM4: library part 3172510040, "C0603 15pF/50V 10%"
CM5 CM10: library part 3170012008, "C0805 10uF/16V 10%"
CP1: library part 3170014011, "C1210 10uF/50V 10%"
CP3: library part ELECTRO1
CP5 CS5 CS8: library part 3170011011, "C0603 10nF/50V  10%"
CP6: library part 3172510028, "C0603 0.22uF/50V 10%"
CR1: library part 53120010024, "5.0*3.2*0.9mm AB 8MHz"
CS1: library part 3172510036, "C0603 1uF/50V 10%"
CS2: library part 3172520028, "C0805 1nF/100V 10%"
DC1: library part 3110050073, "SOT-23 SZNUP2105LT1G"
DF1 DF2 DF5 DF6: library part 3110010015, "SOD-80  LL4148 2A/75V"
DF3 DF4: library part 3110050074, "SOT-23 SM36T1G"
DP1: library part 13110010013, "D0-214AC FM404"
DP4: library part DIODE, "60V,1A,肖特基二极管"
J1 J2 J3 J4 J5 J6 J7 J8 J9 J11: library part 31900010141, "691311500002 2Pin 5.08mm 公头"
LC1: library part 3180020022, "ACT45B-510-2P-TL  10M/1K/0.2A"
LM1 LM2: library part 3180020002, "L0603 ILBB0603ER102V"
LP1: library part 53180020011, "L0805 MPZ2012S221ATD25"
LP2: library part Inductor, "22uH/1.9A"
P1: library part 3190010008, "直针插座 CWF25404D180 4PIN/2.54mm/1A/250V"
QF1 QF2 QF3 QF4 QF5 QF6 QF7 QF8: library part 53110022012, "TO-252-3 FDD86567-F085 60V/100A"
RC1 RM12 RM13 RM14 RM15 RM16: library part 3160030053, "R0603 1/10w 10K 1%"
RC2 RC3: library part 3160050016, "R0805 1/8w10R 1%"
RF1 RF2 RF5 RF6 RF7 RF8 RF13 RF14: library part 3160030193, "R0603 1/10w  10R 1%"
RF3 RF4 RF9 RF11 RM10 RM11: library part 3160030020, "R0603  1/10w 510R 1%"
RF10 RF12: library part 3162380033, "R2512 1W 0.01R 1%"
RM1 RS4 RS9: library part 3160030053, "R0603 1/10w 10K"
RM2 RM6: library part 3160030087, "R0603 1/10w  36K 1%"
RM3 RM7: library part 13162320038, "R0805 1/8w 1.5K 1%最好用1/4w"
RM4 RM8: library part 3162320027, "R0805 1/8w 0.62K 1% 需要1/4w"
RM5 RM9: library part 3160030013, "R0603  1/10w 51R 1%或100欧"
RM17: library part 3160030001, "R0603 1/10w 0R 1%"
RP3: library part RES2, "汽车级电阻，47kΩ"
RS1 RS7 RS10: library part 3160030224, "R0603 1/10w  4.7K 1%"
RS2: library part 3160050008, "R0805 1/8w 100K 1%"
RS3 RS6: library part 13162320037, "R0805 1/8w 4.02K 1%"
RS5: library part 3160030062, "R0603 1/10w 15K 1%"
RS8 RS11: library part 3160030151, "R0603 1/10w 240K 1%"
U1: library part AC7811-LQFP64
UC1: library part 3100050124, "PG-DSO-8 TLE9251VSJ"
UF1 UF2 UF3 UF4: library part 3100050121, "SOIC-8L IRS2007STRPBF"
UF5 UF6: library part 3100100010, "SO-8_NB AD8206YRZ"
UP2: library part 3100050105, "SOT-89 L78L12ABUTR"
ZM1 ZM2: library part 3110010088, "SOT-23 BZX84C5V1"

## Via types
v1: diameter 30, hole 20, Top Layer to Bottom Layer, 182 vias
v2: diameter 25, hole 18, Top Layer to Bottom Layer, 107 vias

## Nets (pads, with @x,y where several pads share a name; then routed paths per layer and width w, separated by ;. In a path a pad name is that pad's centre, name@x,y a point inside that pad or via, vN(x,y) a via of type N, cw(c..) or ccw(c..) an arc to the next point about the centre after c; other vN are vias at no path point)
12V: CP8.1 CP9.1 DF1.1 DF2.1 DF5.1 DF6.1 UF1.1 UF2.1 UF3.1 UF4.1 UP2.1 | length 631.6
  Top Layer w60: 2095,1875 2095,1995 2135,2035 ; 2135,2040 CP8.1@2590,2040
  other v2: 2090,1805 850,1810 1270,1810 1680,1810 2090,1850 850,1855 1270,1855 1680,1855
28V: CP1.1 CP2.1 CP7.1 CP10.1 DP1.1 J2.1 UP4.13 | length 1338.2
  Top Layer w15: v1@3575,2385 3575,2463.52 3576.18,2464.7 UP4.13
  Bottom Layer w60: J2.1 3220,1670 3210,1680 3210,1915 3335,2040 3515,2040 3595,2120 3595,2330
  other v1: 3575,2345 3620,2345 3575,2395
  other v2: 3275,1600 3275,1650 3275,1700
AD_PZT1: CS3.1 RS4.1 U1.19 | length 339.3
  Top Layer w8: RS4.1 CS3.1 1205,2380 1223.39,2398.39 U1.19
AD_PZT2: CS6.1 RS9.1 U1.20 | length 330.3
  Top Layer w8: U1.20 1239.13,2405.87 1260,2385 CS6.1 RS9.1
AD_VBAT1: CS1.1 RS1.1 U1.21 | length 229.2
  Top Layer w8: U1.21 1254.88,2525.12 v2(1285,2495) CS1.1
  Bottom Layer w8: RS1.1 v2(1285,2495)
AVDD: CM9.1 CM10.1 LM2.1 RM17.2 U1.10 | length 200.9
  Top Layer w8: v1(965,2720) RM17.2 1040,2720 1079.91,2759.91 1081.13,2759.91 1082.59,2761.38 U1.10
  Bottom Layer w8: LM2.1@1135,2735 LM2.1@1140,2740
AVDD-IO: CM8.2 RM17.1 U1.11 | length 281.8
  Top Layer w8: RM17.1 1040,2660 1055,2675 1055,2705 1095.63,2745.63 U1.11
  Top Layer w20: CM8.2 955,2655 960,2660 RM17.1
BOOT: RM16.2 U1.55 | length 111.5
  Top Layer w8: RM16.2 1310,3030 1333.62,3006.38 U1.55
CAN1_RX: U1.54 UC1.4 | length 1061.1
  Top Layer w8: U1.54 1349.37,3055.58 1373.79,3080 1703.23,3080 1988.23,2795 UC1.4
CAN1_TX: U1.53 UC1.1 | length 973.4
  Top Layer w8: U1.53 1365.12,3050.12 1380,3065 1695,3065 1760,3000 v2(1760,2990) ; v2(2020,2990) 2045,2990 2090,2945 UC1.1
  Bottom Layer w8: v2(1760,2990) v2(2020,2990)
CANH: DC1.2 J1.2 LC1.4 RC3.2 | length 1148.4
  Top Layer w20: LC1.4 2803.86,2923.86 2855,2975 J1.2
  Bottom Layer w20: RC3.2 2815,2930 2855,2970 J1.2 2855,3375 2870,3390 DC1.2
CANL: DC1.1 J1.1 LC1.3 RC2.2 | length 1666.8
  Top Layer w20: LC1.3@2685,2830 2940,2830 3055,2945 J1.1
  Bottom Layer w20: RC2.2 2940,2830 3055,2945 J1.1 3055,3370 3035,3390 DC1.1
DVDD: CM5.2 CM6.1 CM15.2 LM1.2 U1.35 U1.59 | length 986.6
  Top Layer w8: v2(1251.89,3016.89) 1270.63,2998.15 U1.59 ; U1.35 CM6.1@1600,2698.39
  Top Layer w20: CM6.1 1600,2698.39 v2(1600,2740)
  VCC w20: v2(1251.89,3016.89) 1251.89,2963.11 1265,2950 1430,2950 1470,2910 1470,2815 1545,2740 v2(1600,2740)
  Bottom Layer w20: CM15.2 v2(1251.89,3016.89) ; LM1.2 CM5.2@1580,2670 ; CM5.2 v2(1600,2740)
EXTAL: CM1.1 CR1.1 U1.7 | length 701.1
  Top Layer w8: CM1.1 770,3055 790,3075 860,3075 ; CR1.1 855,3070 860,3075 ; U1.7 1081.38,2808.62 1000,2890 1000,3050 975,3075 860,3075
GND: CC1.2 CC2.1 CC3.2 CF5.2 CF6.2 CF7.2 CF8.2 CM1.2 CM2.1 CM3.1 CM4.2 CM5.1 CM6.2 CM7.1 CM8.1 CM9.2 CM10.2 CM11.2 CM12.1 CM13.1 CM14.1 CM15.1 CR1.2 CR1.4 CS1.2 CS3.2 CS4.2 CS5.2 CS6.2 CS7.2 CS8.2 J7.1 LP1.2 P1.1 RC1.2 RM12.1 RM14.1 RM15.1 RM16.1 RS8.1 RS11.1 U1.9 U1.12 U1.34 U1.58 UC1.2 UF5.2 UF5.3 UF6.2 UF6.3 ZM1.A ZM1.NC ZM2.A ZM2.NC | length 327.9
  Top Layer w8: CM9.2 855,2750 865,2760 921.21,2760 938.34,2777.13 U1.9
  other v1: 2090,2235 2185,2235 2287.5,2235 2390,2235 2142.5,2330 2245,2330 2352.5,2330 2100,2420 2195,2420 2297.5,2420 2400,2420 2147.5,2530 2250,2530 1115,2575
  other v2: 1420,2250 1420,2320 725,2350 820,2350 915,2350 540,2465 1685,2520 1805,2520 1925,2520 650,2655 1275,2685 650,2735 755,2735 1270,2785 1355,2785 1235,2840 1310,2840 1385,2840 770,2920 1075,2930 1760,2955 1920,2955 2010,2955 615,3000 1075,3025 1920,3055 2010,3055 2140,3055 2225,3055 615,3095 2320,3095 2415,3095 1075,3120 510,3140 710,3140 615,3190 510,3235 710,3235 510,3330 710,3330
IINJ1_AD_MCU: CF7.1 U1.22 UF5.5 | length 506.6
  Top Layer w8: U1.22 1270.63,2549.37 1310,2510 1358.79,2510 1468.79,2400 CF7.1 CF7.1@1578,2400
  Top Layer w10: UF5.5 CF7.1@1578,2400
IINJ2_AD_MCU: CF8.1 U1.23 UF6.5 | length 618
  Top Layer w8: U1.23 1286.38,2554.84 1316.21,2525 1365,2525 1450,2440 v2(1505,2440)
  Bottom Layer w10: v2(1505,2440) 1690,2440 1702,2428 1702,2340
MAP1-IN: CS5.1 J11.2 RS7.2 RS8.2 | length 908.6
  Bottom Layer w10: J11.2@240,2390 J11.2 CS5.1 RS8.2 ; RS8.2@445,2390 1030,2390 1057,2417 1057,2442 1075,2460 RS7.2
MAP1_AD_MCU: CS4.1 RS7.1 U1.18 | length 266.9
  Top Layer w8: v2(1170,2420) CS4.1 1195,2460 1207.64,2472.64 U1.18
  Bottom Layer w8: v2(1170,2420) RS7.1
MAP2-IN: CS8.1 J11.1 RS10.2 RS11.2 | length 1030.3
  Bottom Layer w10: J11.1@240,2590 J11.1 CS8.1 RS11.2 520,2590 695,2415 1020,2415 1040,2435 1040,2490 1075,2525 RS10.2 RS10.2@1120,2525
MAP2_AD_MCU: CS7.1 RS10.1 U1.17 | length 125.8
  Top Layer w8: CS7.1 1170,2560 1191.89,2581.89 U1.17
  Bottom Layer w8: RS10.1@1170,2540 v2(1170,2565)
NetCC3_1: CC3.1 RC2.1 RC3.1 | length 194.1
  Bottom Layer w8: CC3.1 2560,2920 2570,2930 RC3.1 RC2.1
NetCF1_1: CF1.1 DF1.2 UF1.8
  other v2: 2281,1780 2311,1810
NetCF2_1: CF2.1 DF2.2 UF2.8
  other v2: 1031,1780 1061,1810
NetCF3_1: CF3.1 DF5.2 UF3.8
  other v2: 1851,1780 1881,1810
NetCF4_1: CF4.1 DF6.2 UF4.8
  other v2: 1456,1780 1486,1810
NetCP6_1: CP6.1 DP1.2 UP2.3 | length 197
  Top Layer w8: CP6.1@2515,1792.02 UP2.3 ; DP1.2@2605,1685 UP2.3@2605,1790.73
NetDP4_K: DP4.K LP2.1 UP4.11 | length 276.7
  Top Layer w15: DP4.K 3485,2405 3525,2445 UP4.11
NetLC1_1: LC1.1 UC1.7 | length 157
  Top Layer w20: UC1.7 2445,2895 2474.91,2924.91 LC1.1
NetLC1_2: LC1.2 UC1.6 | length 150.8
  Top Layer w20: UC1.6 2445,2845 2460.14,2829.86 LC1.2
NetQF1_1: QF1.1 RF1.2 | length 566.6
  Top Layer w15: QF1.1 v2(2165,1185)
  Bottom Layer w15: v2@2165,1195 2165,1405 2205,1445 RF1.2 RF1.2@2205,1665
NetQF2_1: QF2.1 RF2.2 | length 579.9
  Top Layer w15: QF2.1 v2(895,1185)
  Bottom Layer w15: v2(895,1185) 895,1420 955,1480 RF2.2
NetQF3_1: QF3.1 RF5.2 | length 835.1
  Top Layer w15: QF3.1 v2(2350,950)
  Bottom Layer w15: RF5.2 2285,1460 2390,1355 2390,990 v2(2350,950)
NetQF4_1: QF4.1 RF6.2 | length 835.1
  Top Layer w15: QF4.1 v2(1080,950)
  Bottom Layer w15: RF6.2 1035,1380 1130,1285 1130,1030 1080,980 v2(1080,950)
NetQF5_1: QF5.1 RF7.2 | length 586.9
  Top Layer w15: QF5.1 v2(1715,1185)
  Bottom Layer w15: v2(1715,1185) 1715,1425 1780,1490 RF7.2 ; RF7.2@1785,1660 RF7.2@1785,1665
NetQF6_1: QF6.1 RF8.2 | length 591.1
  Top Layer w15: QF6.1 v2(1300,1185)
  Bottom Layer w15: v2(1300,1185) 1300,1440 1375,1515 RF8.2@1375,1665
NetQF7_1: QF7.1 RF13.2 | length 828
  Top Layer w15: QF7.1 v2(1900,950)
  Bottom Layer w15: RF13.2 1855,1440 1950,1345 1950,1000 v2@1905,955
NetQF8_1: QF8.1 RF14.2 | length 833.4
  Top Layer w8: v2(1484.5,950) v2@1485,949.5
  Top Layer w15: QF8.1 v2@1485,949.5
  Bottom Layer w15: RF14.2 1455,1410 1540,1325 1540,1050 1484.5,994.5 v2(1484.5,950)
NetRC1_1: RC1.1 UC1.8
NetRF1_1: RF1.1 UF1.7 | length 136.9
  Top Layer w15: v2(2270,1720) UF1.7@2341.91,1720
  Bottom Layer w15: RF1.1 v2(2270,1720)
NetRF2_1: RF2.1 UF2.7 | length 133.5
  Top Layer w15: v2(1025,1720) 1026.09,1718.91 UF2.7
  Bottom Layer w15: RF2.1@960,1720 v2(1025,1720)
NetRF3_2: RF3.2 UF1.2 UF1.3 | length 160.4
  Top Layer w8: RF3.2 2020,1720 2045,1695 2120,1695
NetRF4_2: RF4.2 UF2.2 UF2.3 | length 150.4
  Top Layer w8: RF4.2 780,1720 805,1695 870,1695
NetRF5_1: RF5.1 UF1.5 | length 94.7
  Top Layer w15: UF1.5 2343,1577 v2(2345,1575)
  Bottom Layer w15: v2(2345,1575) RF5.1
NetRF6_1: RF6.1 UF2.5 | length 86
  Top Layer w15: v2(1095,1575) UF2.5@1095,1611
  Bottom Layer w15: v2(1095,1575) RF6.1
NetRF7_1: RF7.1 UF3.7 | length 138.5
  Top Layer w15: v2(1850,1720) 1916.91,1720 UF3.7
  Bottom Layer w15: RF7.1 v2(1850,1720)
NetRF8_1: RF8.1 UF4.7 | length 145.5
  Top Layer w15: v2(1435,1720) 1436.09,1718.91 UF4.7
  Bottom Layer w15: RF8.1@1380,1715 RF8.1 v2(1435,1720)
NetRF9_2: RF9.2 UF3.2 UF3.3 | length 148.3
  Top Layer w8: RF9.2 1610,1715 1630,1695 1695,1695
NetRF11_2: RF11.2 UF4.2 UF4.3 | length 152.4
  Top Layer w8: RF11.2@1210,1770 1200,1760 1200,1715 1220,1695 1285,1695
NetRF13_1: RF13.1 UF3.5 | length 89.2
  Top Layer w15: v2(1918,1578) UF3.5
  Bottom Layer w15: RF13.1 1915,1581 v2(1918,1578)
NetRF14_1: RF14.1 UF4.5 | length 88.8
  Top Layer w15: v2(1513,1575) UF4.5@1513,1613
  Bottom Layer w15: v2(1513,1575) 1515,1577 RF14.1
NetRM4_1: RM4.1 RM5.2 ZM1.K
NetRM8_1: RM8.1 RM9.2 ZM2.K | length 134.1
  Top Layer w15: ZM2.K v2(760,2655)
  Bottom Layer w15: v2(760,2655) 775,2655 785,2645 RM8.1
NetRP3_2: RP3.2 UP4.5 | length 213.1
  Top Layer w15: UP4.5 RP3.2@3499.41,2949.41
NetRS1_2: RS1.2 RS2.1 RS5.2 | length 1632
  Top Layer w8: RS5.2 RS2.1 615,1845 860,2090 1235,2090 1345,2200 v2(1345,2205)
  Bottom Layer w8: v2(1345,2205) RS1.2
NOZZLE1_M1: CF1.2 DF3.2 J4.2 QF1.3 QF3.2 UF1.6 | length 2215.7
  Top Layer w15: QF1.3@2345,1106.1 v2(2345,1185)
  Top Layer w20: CF1.2 2175,1738.91 2245,1668.91 ; v2(2245,1575) 2245,1668.91 ; UF1.6 2245,1668.91
  Top Layer w65: QF3.2@2265,603.94 2265,1000 QF1.3@2350,1085
  Top Layer w80: 2380,610 2710,610 2860,460 J4.2@2860,250
  Bottom Layer w15: v2(2245,1575) 2245,1450 2345,1350 v2@2345,1195
  other v1: 2199,511 2267,511 2335,511 2166,575 2229.67,575 2293.33,575 2357,575 2199,635 2264,635 2329,635 2166,691 2229.67,691 2293.33,691 2357,691
NOZZLE1_M2: DF3.1 J4.1 RF10.2 UF5.8 | length 3497
  Top Layer w10: UF5.8 1645,2180 1670,2155 v2(1670,2125)
  Top Layer w80: RF10.2@1993.56,344.85 2255.15,344.85 2350,250 ; 2355,245 J4.1
  Bottom Layer w10: v2(1670,2125) 1670,2075 1720,2025 1960,2025 2000.5,1984.5 2000.5,1544.5 2060,1485 2060,180 1987.5,107.5 1912.5,107.5 1890,130 1890,200 1910,220 2005,220 v1@2015,230
  other v1: 2015,220
NOZZLE2_M1: CF2.2 DF4.2 J5.1 QF2.3 QF4.2 UF2.6 | length 2203.3
  Top Layer w15: CF2.2@930,1885 930,1740 1000,1670 ; v2(1000,1575) 1000,1670 ; QF2.3@1075,1105 v2(1075,1185) ; UF2.6@1095,1670 1000,1670
  Top Layer w20: CF2.2@920,1926 CF2.2@925,1926 ; CF2.2@925,1921 CF2.2@930,1926
  Top Layer w65: QF4.2@990,650 990,990 1070,1070 QF2.3@1070,1115
  Top Layer w80: J5.1 605,775 745,635 QF4.2@965,635
  Bottom Layer w15: v2(1000,1575) 1000,1365 1075,1290 v2(1075,1185)
  other v1: 934,511 1002,511 1070,511 901,575 964.67,575 1028.33,575 1092,575 934,635 999,635 1064,635 901,691 964.67,691 1028.33,691 1092,691
NOZZLE2_M2: DF4.1 J5.2 RF12.2 UF6.8 | length 3660.1
  Top Layer w80: J5.2 545,575 790,330 RF12.2@1175,330
  Bottom Layer w10: v1(1205,220) 1290,220 1315,195 1315,140 1355,100 1355.96,100 1365.46,90.5 1510.5,90.5 1602,182 1602,1002 1680,1080 1680,1460 1607.5,1532.5 1607.5,2137.5 1645,2175 UF6.8
PGND: C1.2 C2.2 C3.2 CP1.2 CP2.2 CP3.2 CP4.2 CP5.2 CP6.2 CP7.2 CP8.2 CP9.2 CP10.2 CS2.2 DC1.3 DF3.3 DF4.3 DP4.A J2.2 J3.1 LP1.1 QF3.3 QF4.3 QF7.3 QF8.3 RP3.1 RS5.1 UF1.4 UF2.4 UF3.4 UF4.4 UP2.2 UP4.0 UP4.1 UP4.2 UP4.3 UP4.4 UP4.6 UP4.8 UP4.9 UP4.10 UP4.12 UP4.14 | length 171
  Top Layer w15: UP4.12 UP4.0@3550.59,2585 ; UP4.14 v1@3601.77,2582.7 ; v1@3612.5,2585.93 3617.5,2590.93 v1@3617.5,2630 ; v1@3614.27,2582.7 v1@3617.5,2585.93
  other v1: 2617.5,755 2720,755 2827.5,755 2930,755 3032.5,755 2116,805 841,810 1246,810 1661,810 2485,845 2575,845 2670,845 2772.5,845 2875,845 2982.5,845 3085,845 2116,848.5 841,853.5 1246,853.5 1661,853.5 2116,892 841,897 1246,897 1661,897 2485,947.5 2575,947.5 110,995 205,995 307.5,995 410,995 517.5,995 620,995 2485,1050 162.5,1090 265,1090 372.5,1090 475,1090 577.5,1090 120,1180 215,1180 317.5,1180 420,1180 527.5,1180 630,1180 2435,1525 2525,1525 1160,1540 1235,1540 1315,1540 1650,1550 1730,1550 685,1560 775,1560 2075,1560 2155,1560 2435,1612.5 1160,1637.5 1235,1637.5 685,1662.5 775,1662.5 2435,1715 685,1765 3730,2070 2957.5,2145 3070,2145 3182.5,2145 3680,2155 3730,2245 3145,2270 2915,2275 3030,2275 3355,2290 3465,2290 3685,2345 2840,2560 2970,2560 3440,2585 3610,2585.93 3440,2625 3610,2630 3440,2675 3610,2675 3595,2905 3255,3110 3350,3110 3445,3110 3540,3110 3300,3200 3397.5,3200 3495,3200
PZT1-IN: J9.1 RS3.2 RS4.2 | length 1060.9
  Top Layer w10: v2(1085,2260) RS4.2
  Bottom Layer w10: J9.1@255,2140 725,2140 845,2260 v2(1085,2260) 1100,2260 1115,2245 RS3.2
PZT2-IN: J9.2 RS6.2 RS9.2 | length 1277.2
  Top Layer w10: v2(1250,2200) 1270,2200 1285,2215 RS9.2
  Bottom Layer w10: J9.2 605,1935 870,2200 v2(1250,2200) 1270,2200 1285,2215 RS6.2@1285,2260
RESET: CM2.2 RM1.1 U1.26 | length 160.6
  Top Layer w8: U1.26@1333.62,2625 1333.62,2673.62 v2(1335,2675)
  Bottom Layer w8: v2(1335,2675) 1380,2675 RM1.1 CM2.2
RX1: CM3.2 RM2.1 RM3.1 U1.41 | length 350.7
  Top Layer w8: U1.41 1547.87,2792.87 1565,2810 v2(1610,2810)
  Bottom Layer w8: v2(1610,2810) 1650,2850 RM2.1 ; RM2.1@1690,2845 RM2.1@1695,2845 ; CM3.2 1790,2850 1800,2860 1800,2875 1815,2890 RM3.1
RX2: CM12.2 RM6.1 RM7.1 U1.15 | length 385.1
  Top Layer w8: v2(970,2525) 1005,2525 1085,2605 1085,2670 1097.64,2682.64 U1.15
  Top Layer w15: CM12.2 v2(970,2525)
  Bottom Layer w15: RM6.1 v2(970,2525)
RXD1: J6.2 RM3.2 | length 524
  Bottom Layer w8: RM3.2 2005,2890 2075,2960 J6.2@2075,3305
RXD2: J8.2 RM7.2 | length 748.6
  Bottom Layer w15: J8.2@240,2865 250,2865 275,2840 455,2840 535,2760 535,2635 680,2490 RM7.2
SWCLK: RM10.2 RM12.2 U1.50 | length 301.4
  Top Layer w8: U1.50 1412.36,2997.36 v2(1435,3020)
  Bottom Layer w8: RM10.2 RM12.2 1410,3090 1435,3065 v2(1435,3020)
SWCLK-IN: P1.3 RM10.1 | length 120
  Bottom Layer w8: RM10.1 P1.3
SWDIO: RM11.2 RM13.2 U1.52 | length 252
  Top Layer w8: U1.52 1380.87,2990.87 1395,3005 v2(1395,3030)
  Bottom Layer w8: RM11.2 1360,3065 v2(1395,3030) RM13.2
SWDIO-IN: P1.2 RM11.1 | length 268.6
  Bottom Layer w8: P1.2 1210,3210 1255,3165 RM11.1
T1_H: RF3.1 U1.47 | length 1500.2
  Top Layer w8: U1.47 1851.28,2887.36 2020,2718.64 RF3.1
T1_N: RF9.1 U1.46 | length 1812.9
  Top Layer w8: U1.46 1845.81,2871.61 2005,2712.43 2005,2082.57 1942.43,2020 1645,2020 1610,1985 RF9.1
T2_H: RF4.1 U1.44 | length 2537.7
  Top Layer w8: RF4.1 780,1955 875,2050 1930,2050 1975,2095 1975,2700 1834.88,2840.12 U1.44
T2_N: RF11.1 U1.45 | length 2165.7
  Top Layer w8: RF11.1@1210,1830 1200,1840 1200,1955 1280,2035 1936.21,2035 1990,2088.79 1990,2706.21 1840.35,2855.87 U1.45
TX1: CM7.2 RM5.1 U1.40 | length 285.3
  Top Layer w8: U1.40 v2@1582.87,2777.13 ; v2(1582.87,2778.62) 1584.25,2780 v2@1585,2779.25
  Bottom Layer w8: v2(1582.87,2778.62) 1584.25,2780 CM7.2 RM5.1
TX2: CM13.2 RM9.1 U1.14 | length 367.7
  Top Layer w8: v2(965,2590) 1048.79,2590 1070,2611.21 1070,2690 1078.39,2698.39 U1.14
  Top Layer w15: CM13.2 v2(965,2590)
  Bottom Layer w15: RM9.1 v2(965,2590)
TXD1: J6.1 RM4.2 | length 782.1
  Bottom Layer w8: RM4.2 2125,2785 2275,2935 J6.1@2275,3305
TXD2: J8.1 RM8.2 | length 748.1
  Bottom Layer w15: J8.1@250,3065 275,3040 395,3040 590,2845 590,2660 655,2595 RM8.2@695,2595
UART1_CTS: RM14.2 U1.62 | length 111.4
  Top Layer w8: RM14.2 1200,3020 1223.39,2996.61 U1.62
UART1_RTS: RM15.2 U1.31 | length 140.2
  Top Layer w8: U1.31 1412.36,2562.64 1445,2530 RM15.2@1485,2530
VBAT: C1.1 C2.1 CS2.1 J3.2 QF1.2 QF2.2 QF5.2 QF6.2 RS2.2 | length 127.1
  Top Layer w10: RS2.2@695,1435 RS2.2 CS2.1 695,1315 CS2.1@700,1310
  other v1: 1190,1261 1600,1266 2015,1266 1190,1319.67 1600,1324.67 2015,1324.67 1190,1378.33 1600,1383.33 2015,1383.33 1190,1437 1600,1442 2015,1442
VCC: C3.1 CC1.1 CC2.2 CF5.1 CF6.1 CM11.1 CM14.2 CP3.1 CP4.1 CP5.1 J7.2 LM1.1 LM2.2 LP2.2 P1.4 RM1.2 RM2.2 RM6.2 RM13.1 RS3.1 RS6.1 UC1.3 UC1.5 UF5.6 UF5.7 UF6.6 UF6.7 UP4.7 | length 3204.5
  Top Layer w20: J7.2 1625,3187.93 1967.93,2845 CC2.2 CC1.1 UC1.3 2265,2845 2315,2795 UC1.5@2390,2795
  Top Layer w40: UC1.5@2390,2790 2430,2790 2517.58,2702.42 3063,2702.42
  Bottom Layer w20: RM6.2 v2(975,2465) ; v1(1100,2325) RS3.1 RS6.1 ; v1(1130,2630) LM2.2 1200,2670 1260,2730 RM1.2 ; CM11.1@1455,2735 RM13.1@1455,2940 ; RM13.1 1550,2955 1595,2910 RM2.2 1690,3122.93 1625,3187.93 J7.2
  other v2: 1635,2230 1635,2270
VIINJ1S-: CF3.2 QF5.3 QF7.2 RF10.1 UF3.6 UF5.1 | length 4327.5
  Top Layer w10: v2(1720,2125) 1720,2165 1735,2180 UF5.1 ; UF5.1@1795,2185 UF5.1@1800,2185
  Top Layer w15: CF3.2@1740,1928.5 CF3.2@1750,1918.5 ; CF3.2 1760,1728.91 1820,1668.91 ; v2(1820,1575) 1820,1668.91 ; QF5.3 1900,1108.9 v2(1900,1185) ; UF3.6 1820,1668.91
  Top Layer w65: QF7.2@1820,570 1810,580 1810,995 QF5.3@1890,1075
  Bottom Layer w10: v2(1720,2125) 1720,2065 1742.32,2042.68 1967.32,2042.68 2017.5,1992.5 2017.5,1551.54 2077,1492.04 2077,172 1995.5,90.5 1904.5,90.5 1870,125 1870,195 1845,220 1755,220 v1@1745,230
  Bottom Layer w15: v2(1820,1575) 1820,1410 1900,1330 v2(1900,1185)
  other v1: 1745,220 1749,511 1817,511 1885,511 1716,575 1779.67,575 1843.33,575 1907,575 1749,635 1814,635 1879,635 1716,691 1779.67,691 1843.33,691 1907,691
VIINJ2S-: CF4.2 QF6.3 QF8.2 RF12.1 UF4.6 UF6.1 | length 4092
  Top Layer w15: CF4.2@1340,1928.5 CF4.2@1355,1913.5 ; CF4.2 1350,1735 1416.09,1668.91 1425,1668.91 ; v2(1420,1575) 1420,1663.91 1425,1668.91 ; QF6.3 v2(1481.1,1185) ; UF4.6 1425,1668.91
  Top Layer w65: QF8.2 1394.45,984.45 1480,1070 QF6.3@1480,1105
  Bottom Layer w10: v1(1445,220) 1365,220 1340,195 1340,140 1372.5,107.5 1503.46,107.5 1585,189.04 1585,1009.04 1663,1087.04 1663,1452 1590.5,1524.5 1590.5,2134.5 1550,2175 UF6.1
  Bottom Layer w15: v2(1420,1575) 1420,1380 1481.1,1318.9 v2(1481.1,1185)
  other v1: 1334,511 1402,511 1470,511 1301,575 1364.67,575 1428.33,575 1492,575 1334,635 1399,635 1464,635 1301,691 1364.67,691 1428.33,691 1492,691
XTAL: CM4.1 CR1.3 U1.8 | length 485
  Top Layer w8: CM4.1 770,2800 790,2780 920,2780 941.61,2801.61 CR1.3 950.94,2840 1020,2840 1067.13,2792.87 U1.8
pads on no net: U1.1 U1.2 U1.3 U1.4 U1.5 U1.6 U1.13 U1.16 U1.24 U1.25 U1.27 U1.28 U1.29 U1.30 U1.32 U1.33 U1.36 U1.37 U1.38 U1.39 U1.42 U1.43 U1.48 U1.49 U1.51 U1.56 U1.57 U1.60 U1.61 U1.63 U1.64 UF5.4 UF6.4

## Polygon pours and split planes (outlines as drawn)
VCC on VCC "AutoNaming" (solid, remove dead copper, pour order 42): 915,2690 1165,2690 1165,2620 1165,2515 1785,2520 1860,2520 1855,2515 1855,2150 1435,2150 1020,2150 1020,2325 725,2325 725,2475 725,2690
GND on VCC "AutoNaming" (solid, remove dead copper, pour order 52): 0,1779.12 565,1779.12 565,2014.12 565,2069.12 565,2160 1377.41,2160 1720.01,2160 2065.88,2160 2710,2160 2710,2804.12 2710,3554.12 2705,3559.12 -15,3559.12
PGND on VCC "AutoNaming" (solid, remove dead copper, pour order 56): -420,3750 -95,3425 -95,-390 4100,-390 3905,-195 3905,3870
GND on Top Layer "AutoNaming" (solid, remove dead copper, pour order 44): 0,1780 565,1780 565,2015 565,2070 565,2160.88 1377.41,2160.88 1720.01,2160.88 2065.88,2160.88 2710,2160.88 2710,2805 2710,3555 2705,3560 -15,3560
PGND on Top Layer "AutoNaming" (solid, remove dead copper, pour order 62): -445,3825 -415,3795 -415,25 -415,-585 -350,-650 -160,-460 4280,-460 4280,3610 3850,4040 3715,4175 215,4175
GND on GND "AutoNaming" (solid, remove dead copper, pour order 48): -2.38,1777.36 562.62,1777.36 562.62,2012.36 562.62,2067.36 562.62,2158.23 1375.03,2158.23 1717.63,2158.23 2063.5,2158.24 2707.62,2158.23 2707.62,2802.36 2707.62,3552.36 2702.62,3557.36 -17.38,3557.36
PGND on GND "AutoNaming" (solid, remove dead copper, pour order 54): -165,3800 -165,-275 -180,-290 -115,-225 4130,-225 4130,3530 3940,3720
GND on Bottom Layer "AutoNaming" (solid, remove dead copper, pour order 50): 1.89,1777.47 566.89,1777.47 566.89,2012.47 566.89,2067.47 566.89,2158.35 1379.3,2158.35 1721.9,2158.35 2067.77,2158.35 2711.89,2158.35 2711.89,2802.47 2711.89,3552.47 2706.89,3557.47 -13.11,3557.47
PGND on Bottom Layer "AutoNaming" (solid, remove dead copper, pour order 58): -225,3600 -225,-195 -355,-325 -335,-345 4530,-345 4530,3135 3825,3840

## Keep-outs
Keep-Out Layer:
  circle w10: c3582.68,3346.46 r98.43
  circle w10: c3582.68,196.85 r98.43
  circle w10: c196.85,196.85 r98.43
  circle w10: c196.85,3346.46 r98.43
  lines w20: 0,0 0,3543.31 3779.53,3543.31 3779.53,0 0,0

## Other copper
Top Layer:
  rectangle net VCC: 3390,2705 3455,2770
  rectangle net VCC: 2920,2720 3260,2790
  rectangle net VCC: 2835,2655 2920,2790
  rectangle net VCC: 2880,2680 3390,2730
  rectangle net VCC: 3190,2715 3260,3030
  rectangle net 28V: 3550,2320 3635,2415
  rectangle net NetDP4_K: 3165,2520 3390,2580
  rectangle net NetDP4_K: 3305,2385 3380,2570
  rectangle net NOZZLE2_M1: 863,468 1120,734
  rectangle net VBAT: 670,1235 3570,1480
  rectangle net NOZZLE1_M2: 1935,200 2080,430
  rectangle net VIINJ2S-: 1395,200 1522,468
  rectangle net VIINJ1S-: 1678,200 1805,468
  rectangle net NOZZLE1_M1: 2128,468 2385,734
  rectangle net VIINJ1S-: 1678,468 1935,734
  rectangle net VIINJ2S-: 1263,468 1520,734
  rectangle net NetCF1_1: 2265,1755 2385,1949
  rectangle net NetCF3_1: 1835,1755 1955,1949
  rectangle net NetCF4_1: 1440,1755 1560,1949
  rectangle net NetCF2_1: 1015,1755 1135,1949
  rectangle net 12V: 830,1760 884.78,1890
  rectangle net 12V: 830,1755 900,1795
  rectangle net 12V: 1250,1760 1304.78,1885
  rectangle net 12V: 1250,1755 1320,1795
  rectangle net 12V: 2070,1755 2150,1795
  rectangle net 12V: 1660,1755 1730,1795
  rectangle net 12V: 1660,1760 1714.78,1890
  rectangle net 12V: 2070,1755 2124.78,1890
  rectangle net NOZZLE1_M1: 2310,1035 2390,1165
  rectangle net VIINJ1S-: 1860,1035 1940,1165
  rectangle net VIINJ2S-: 1435,1035 1515,1165
  rectangle net NOZZLE2_M1: 1030,1040 1110,1165
  rectangle net NOZZLE2_M2: 1110,200 1255,420
  rectangle net AVDD: 900,2700 1035,2740
  rectangle net VCC: 1480,2215 1605,2255
  rectangle net VCC: 1550,2215 1650,2295
  rectangle net NetRF11_2: 1260,1665 1320,1725
  rectangle net NetRF4_2: 840,1665 900,1725
  rectangle net NetRF9_2: 1665,1665 1725,1725
  rectangle net NetRF3_2: 2090,1665 2150,1725
  rectangle net 12V: 2510,1895 2645,2085
  rectangle net 28V: 2745,1640 3530,1710
  rectangle net 28V: 3445,1615 3550,1765
  rectangle net NetCP6_1: 2500,1625 2645,1810
  rectangle net NetRC1_1: 2375,2930 2425,3035
  rectangle net NetRC1_1: 2360,2930 2425,2960
  rectangle net 28V: 2740,1570 3545,1715
  rectangle net PGND: 822,791 929,918
  rectangle net PGND: 1227,791 1334,918
  rectangle net PGND: 1642,791 1749,918
  rectangle net VCC: 2360,2770 2410,2810
  rectangle net PGND: 2097,786 2204,913
  pour cut-out: 1255,465 1395,468 1395,425 1395,192.86 1255,192.86
  pour cut-out: 1805,468 1935,460.86 1935,192.86 1805,192.86
VCC:
  rectangle net VBAT: 1010,1235 3580,1480
  rectangle net NOZZLE1_M1: 2137,470 2384,734
  rectangle net VIINJ1S-: 1687,470 1934,734
  rectangle net VIINJ2S-: 1260,470 1519,734
  rectangle net NOZZLE2_M1: 865,470 1119,734
  rectangle net 12V: 830,1830 2125,1925
  rectangle net 12V: 830,1755 885,1875
  rectangle net 12V: 1250,1755 1305,1875
  rectangle net 12V: 1660,1755 1715,1875
  rectangle net 12V: 2070,1755 2125,1875
GND:
  rectangle net VBAT: 865,1235 2350,1480
  rectangle net NOZZLE1_M1: 2130,469 2385,734
  rectangle net VIINJ1S-: 1680,469 1935,734
  rectangle net VIINJ2S-: 1265,469 1520,734
  rectangle net NOZZLE2_M1: 865,469 1120,734
Bottom Layer:
  rectangle net 28V: 3550,2320 3635,2415
  rectangle net 28V: 3565,2320 3630,2530
  rectangle net NOZZLE1_M1: 2129,470 2384,733
  rectangle net VIINJ1S-: 1679,470 1934,733
  rectangle net VIINJ2S-: 1264,470 1519,733
  rectangle net NOZZLE2_M1: 864,470 1119,733
  rectangle net 12V: 830,1790 960,1930
  rectangle net 12V: 1250,1785 1380,1925
  rectangle net 12V: 1660,1790 1790,1930
  rectangle net 12V: 2070,1785 2200,1925
  rectangle net NetRM8_1: 770,2575 870,2600
  rectangle net RX2: 815,2460 865,2540
  rectangle net RX2: 820,2510 930,2540
  rectangle net NetCF2_1: 1015,1755 1080,1945
  rectangle net NetCF4_1: 1440,1755 1505,1945
  rectangle net NetCF3_1: 1835,1755 1900,1945
  rectangle net NetCF1_1: 2265,1755 2330,1945
  rectangle net NOZZLE1_M2: 2595,125 2740,295
  rectangle net NOZZLE1_M1: 2780,125 2915,295
  region net NOZZLE2_M1: 380,690 380,835 210,835 210,690
  region net NOZZLE2_M2: 380,515 380,660 210,660 210,515
  rectangle net AVDD: 945,2700 1060,2740
  rectangle net VCC: 1620,2215 1735,2290
  rectangle net VCC: 1715,2215 1795,2250
  rectangle net NetCC3_1: 2540,2885 2650,2960
  rectangle net NetCC3_1: 2610,2800 2650,2940
  rectangle net VCC: 1360,2715 1530,2750
  rectangle net NetRM4_1: 1740,2700 1875,2735
  rectangle net NetRM4_1: 1825,2680 1875,2815
  rectangle net RX1: 1675,2835 1780,2865
  rectangle net VCC: 1375,3270 1670,3360
  rectangle net AVDD: 1050,2720 1135,2740
  rectangle net VCC: 1380,3190 1430,3345
  rectangle net 28V: 3155,1575 3555,1715

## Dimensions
3779.53,3543.31 to 3779.53,0 on Keep-Out Layer
0,3543.31 to 3779.53,3543.31 on Keep-Out Layer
